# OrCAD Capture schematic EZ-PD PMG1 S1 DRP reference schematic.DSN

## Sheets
1 03. Step Down Regulators: size A3; title: PMG1-S1 DRP REFERENCE DESIGN; rev: 01; note: 630-XXXXX-XX
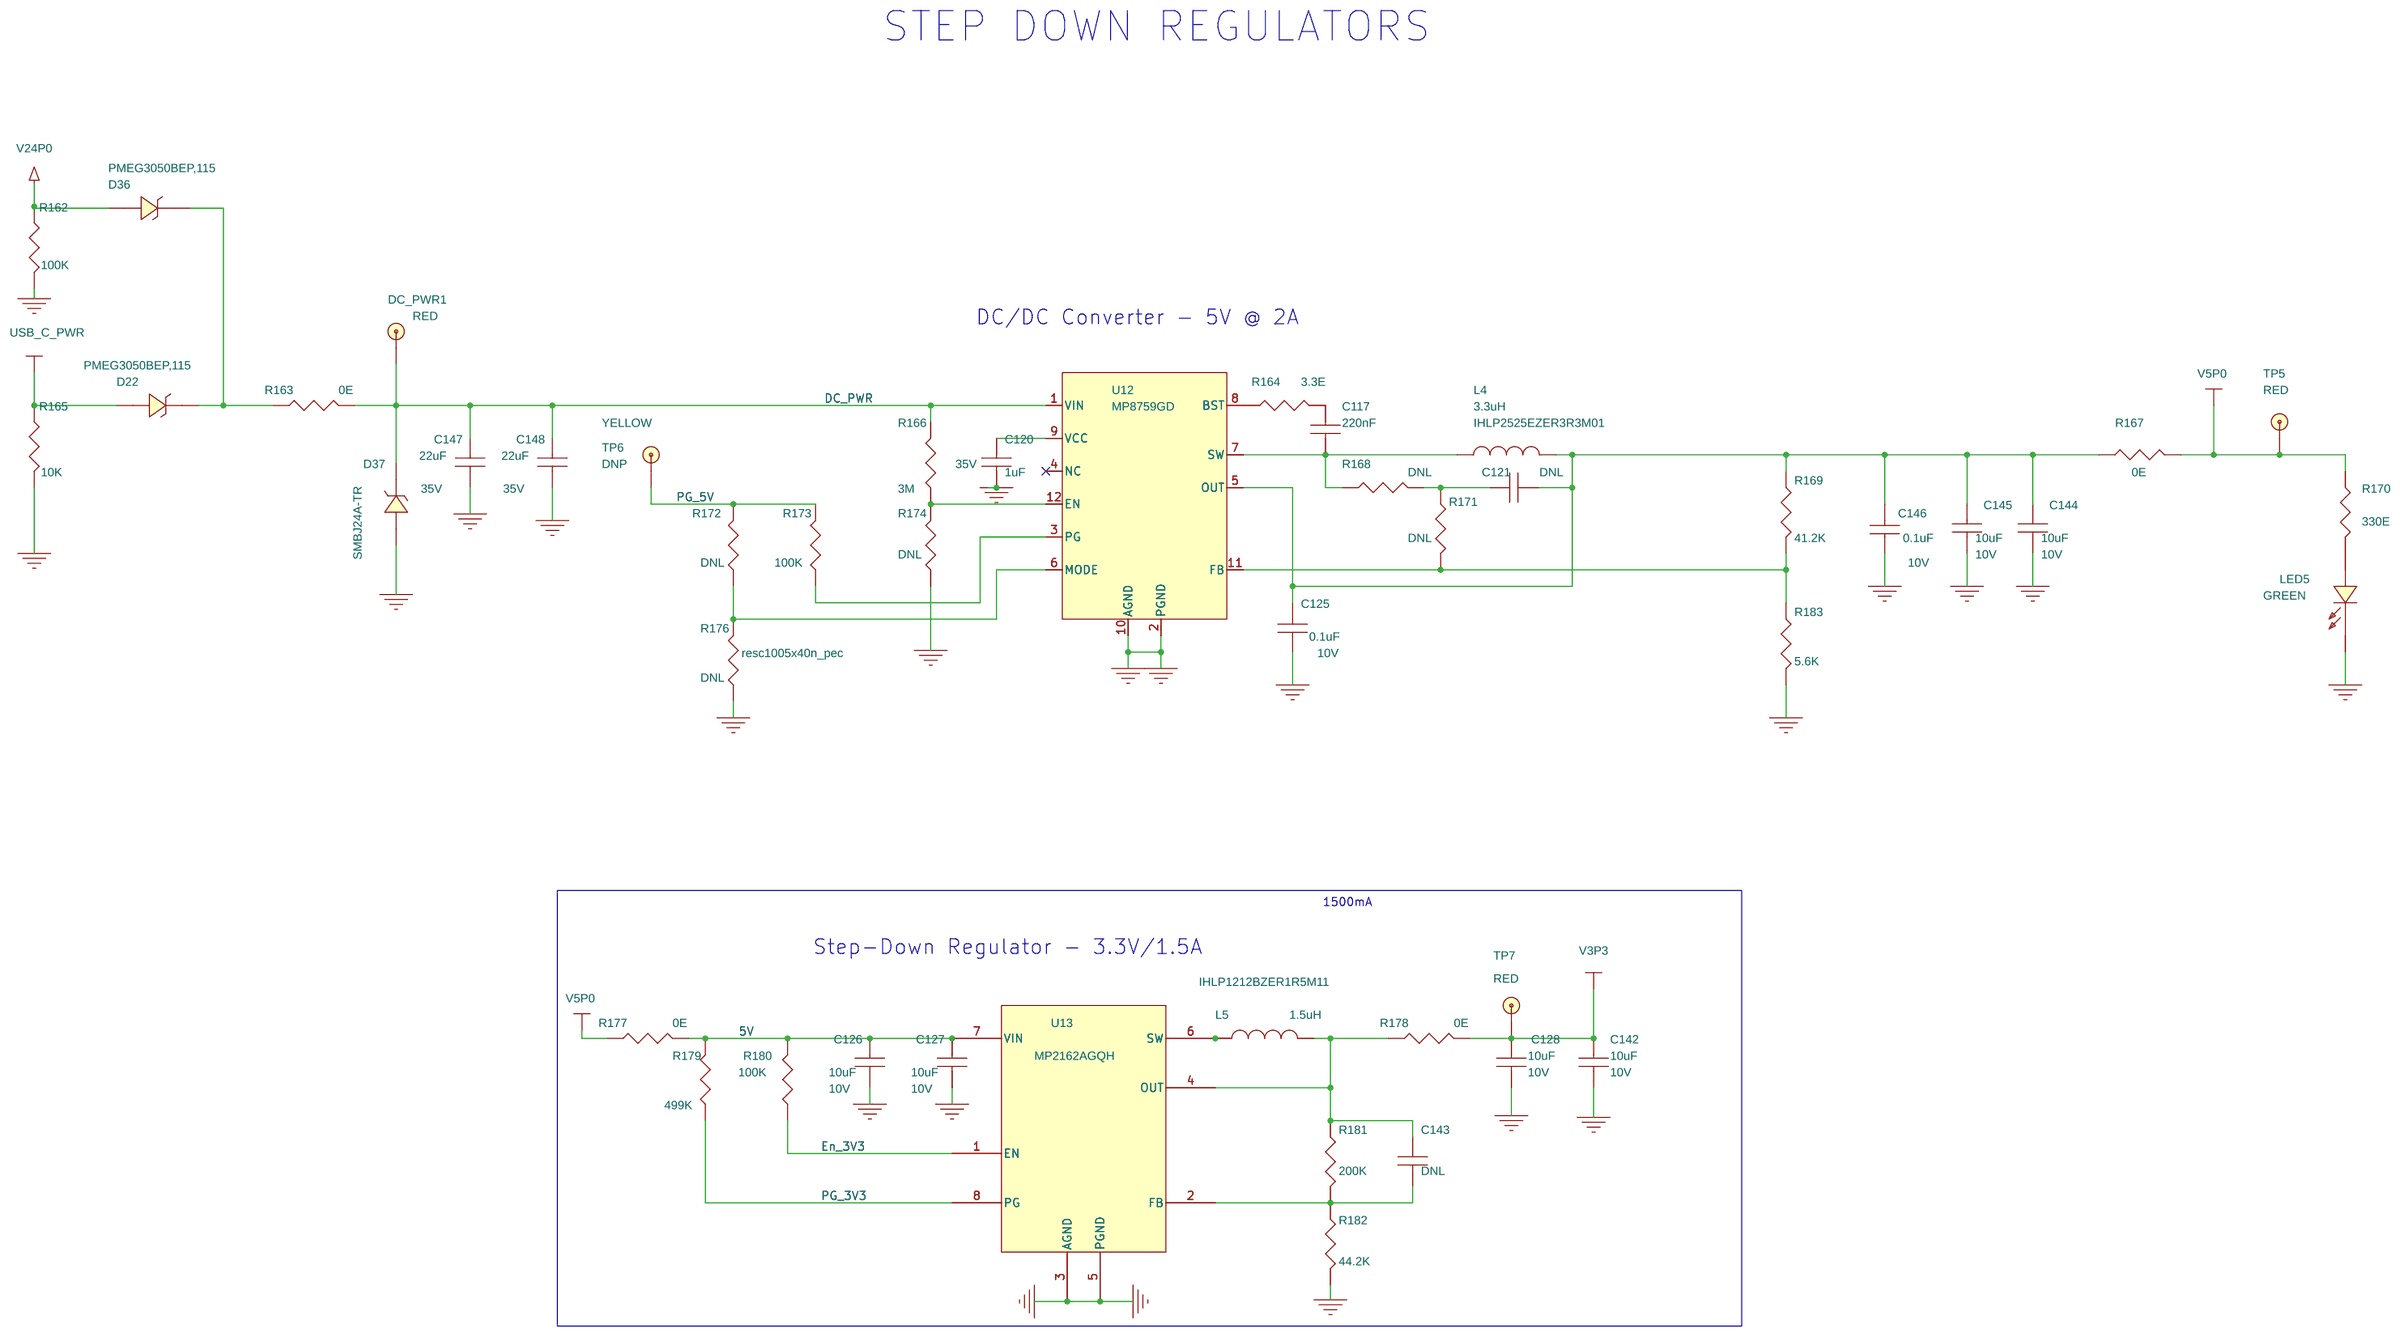
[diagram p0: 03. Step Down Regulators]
2 01. Title Page
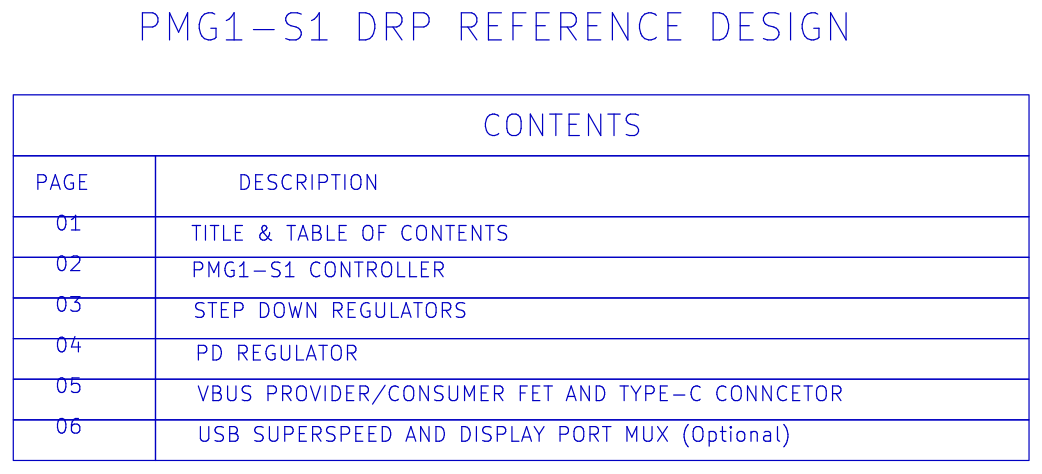
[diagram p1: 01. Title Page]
3 02. PMG1-S1 Controller: size A3
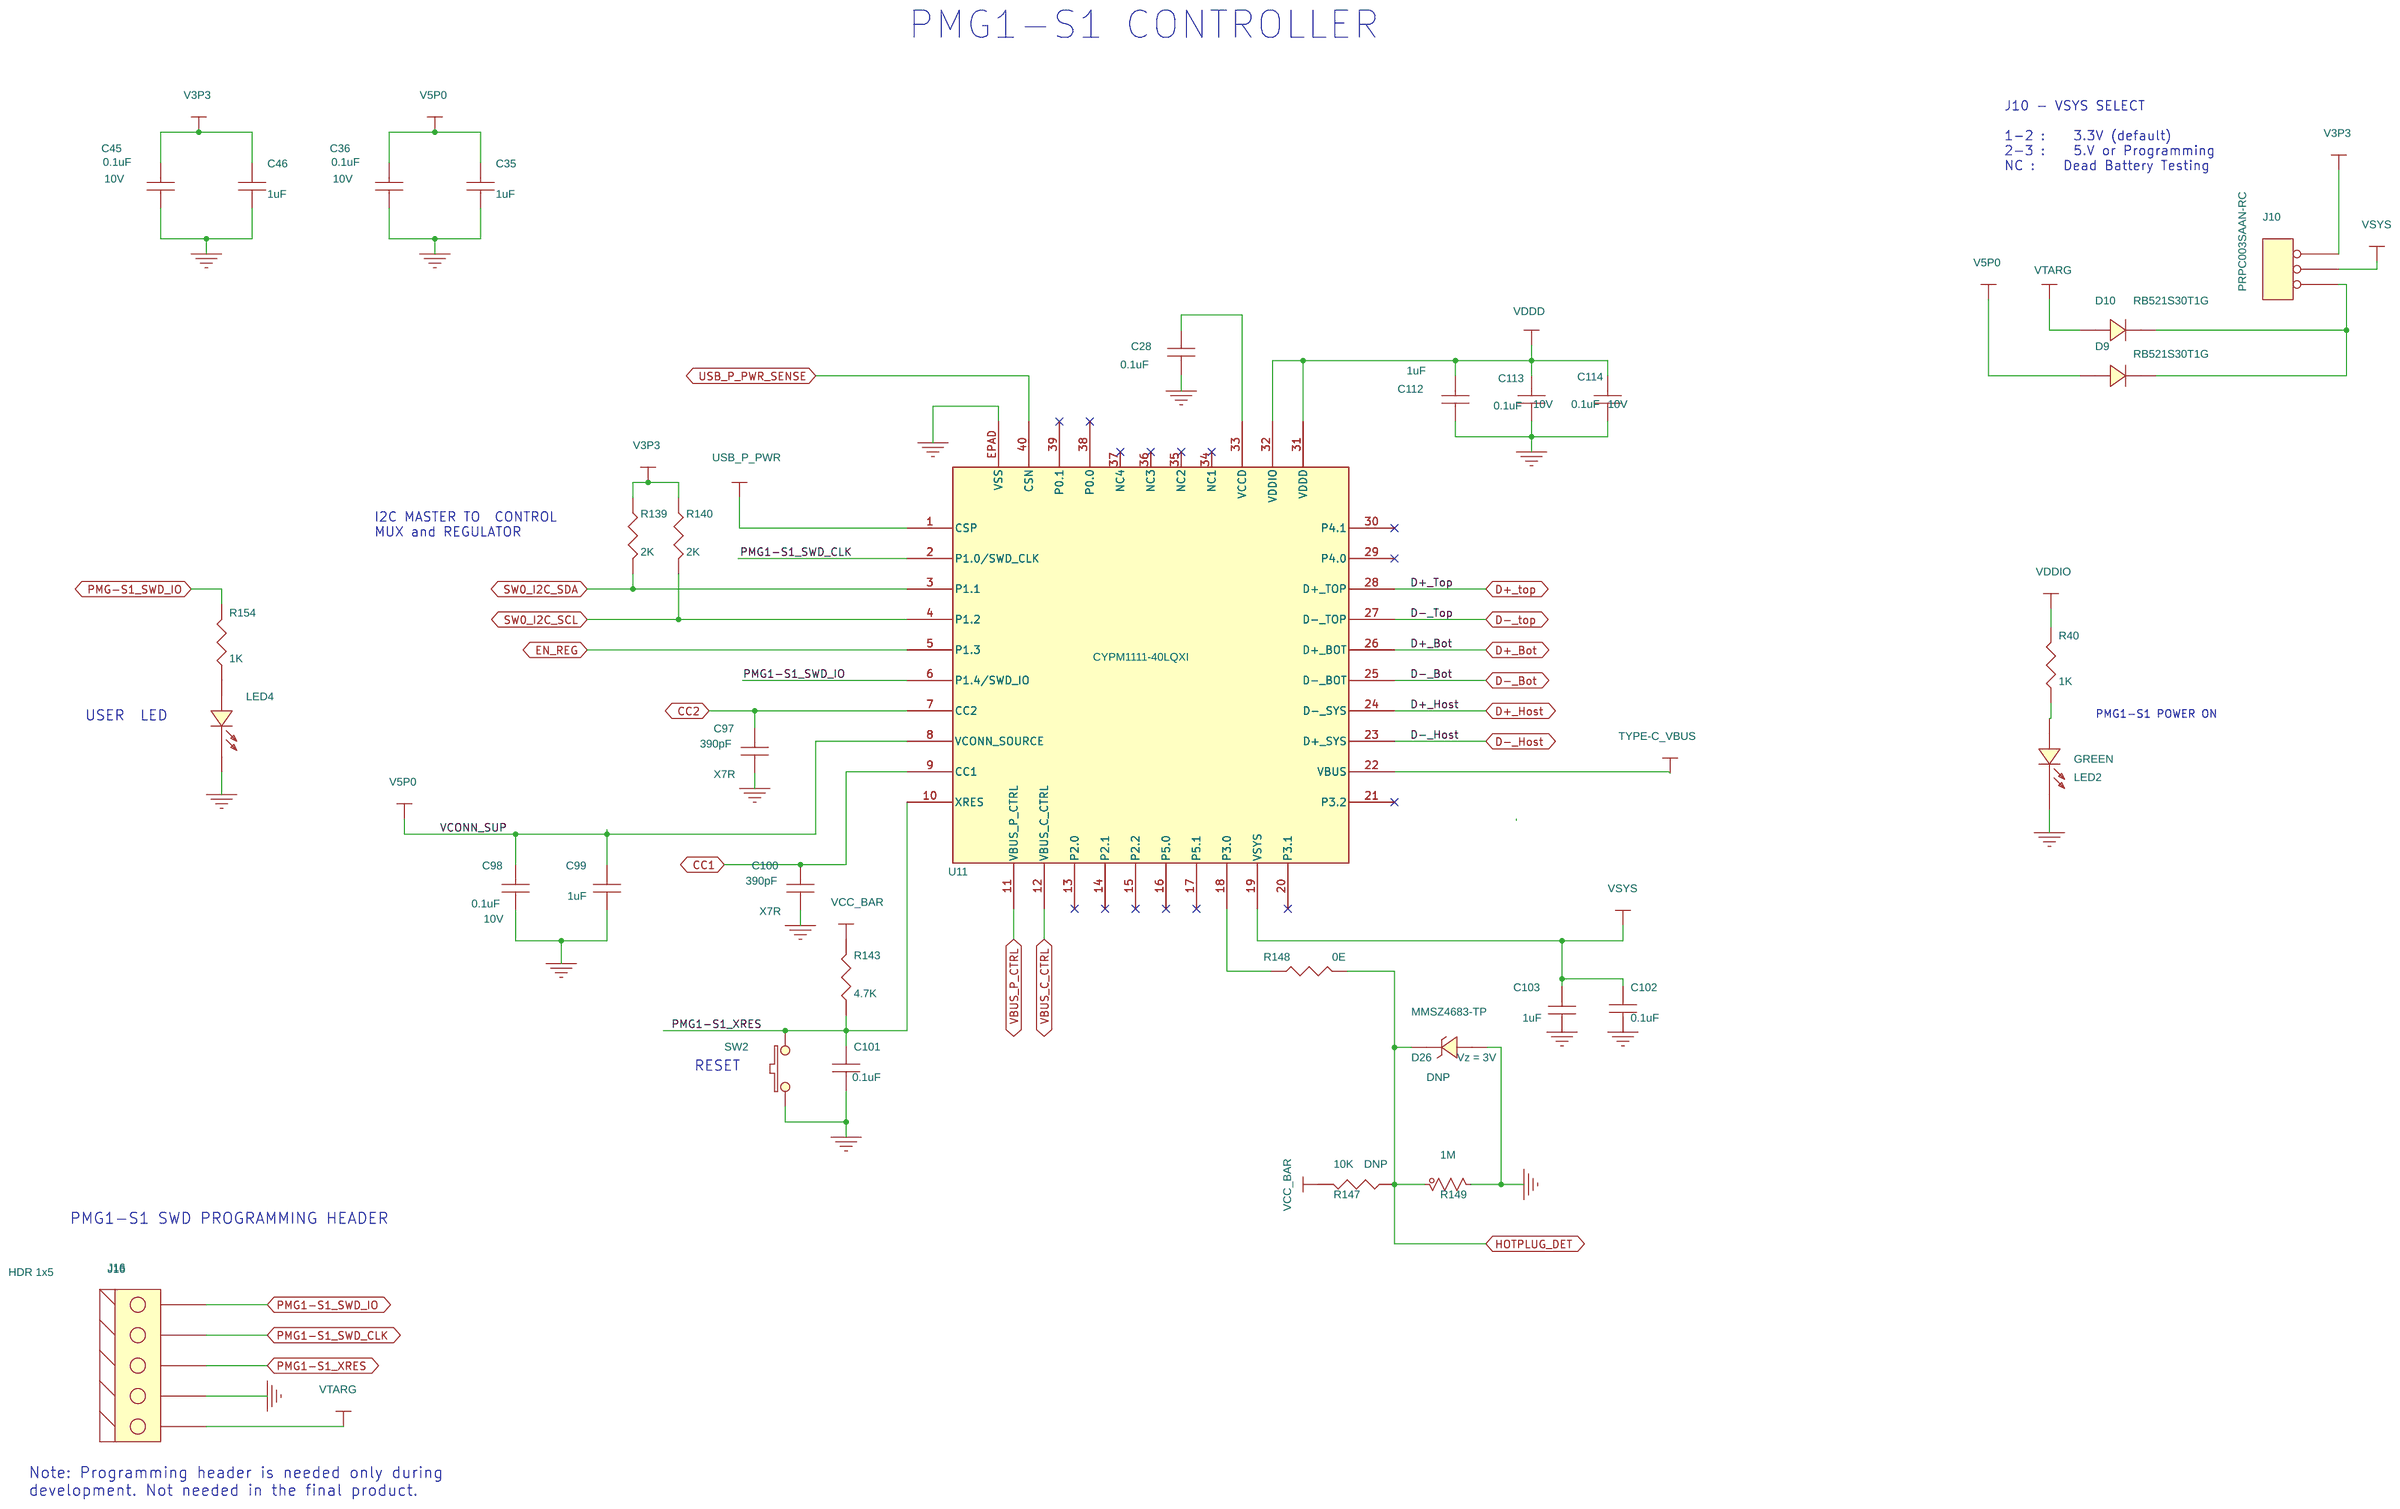
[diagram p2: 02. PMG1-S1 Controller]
4 06. PERICOM_MUX (OPTIONAL): size A3
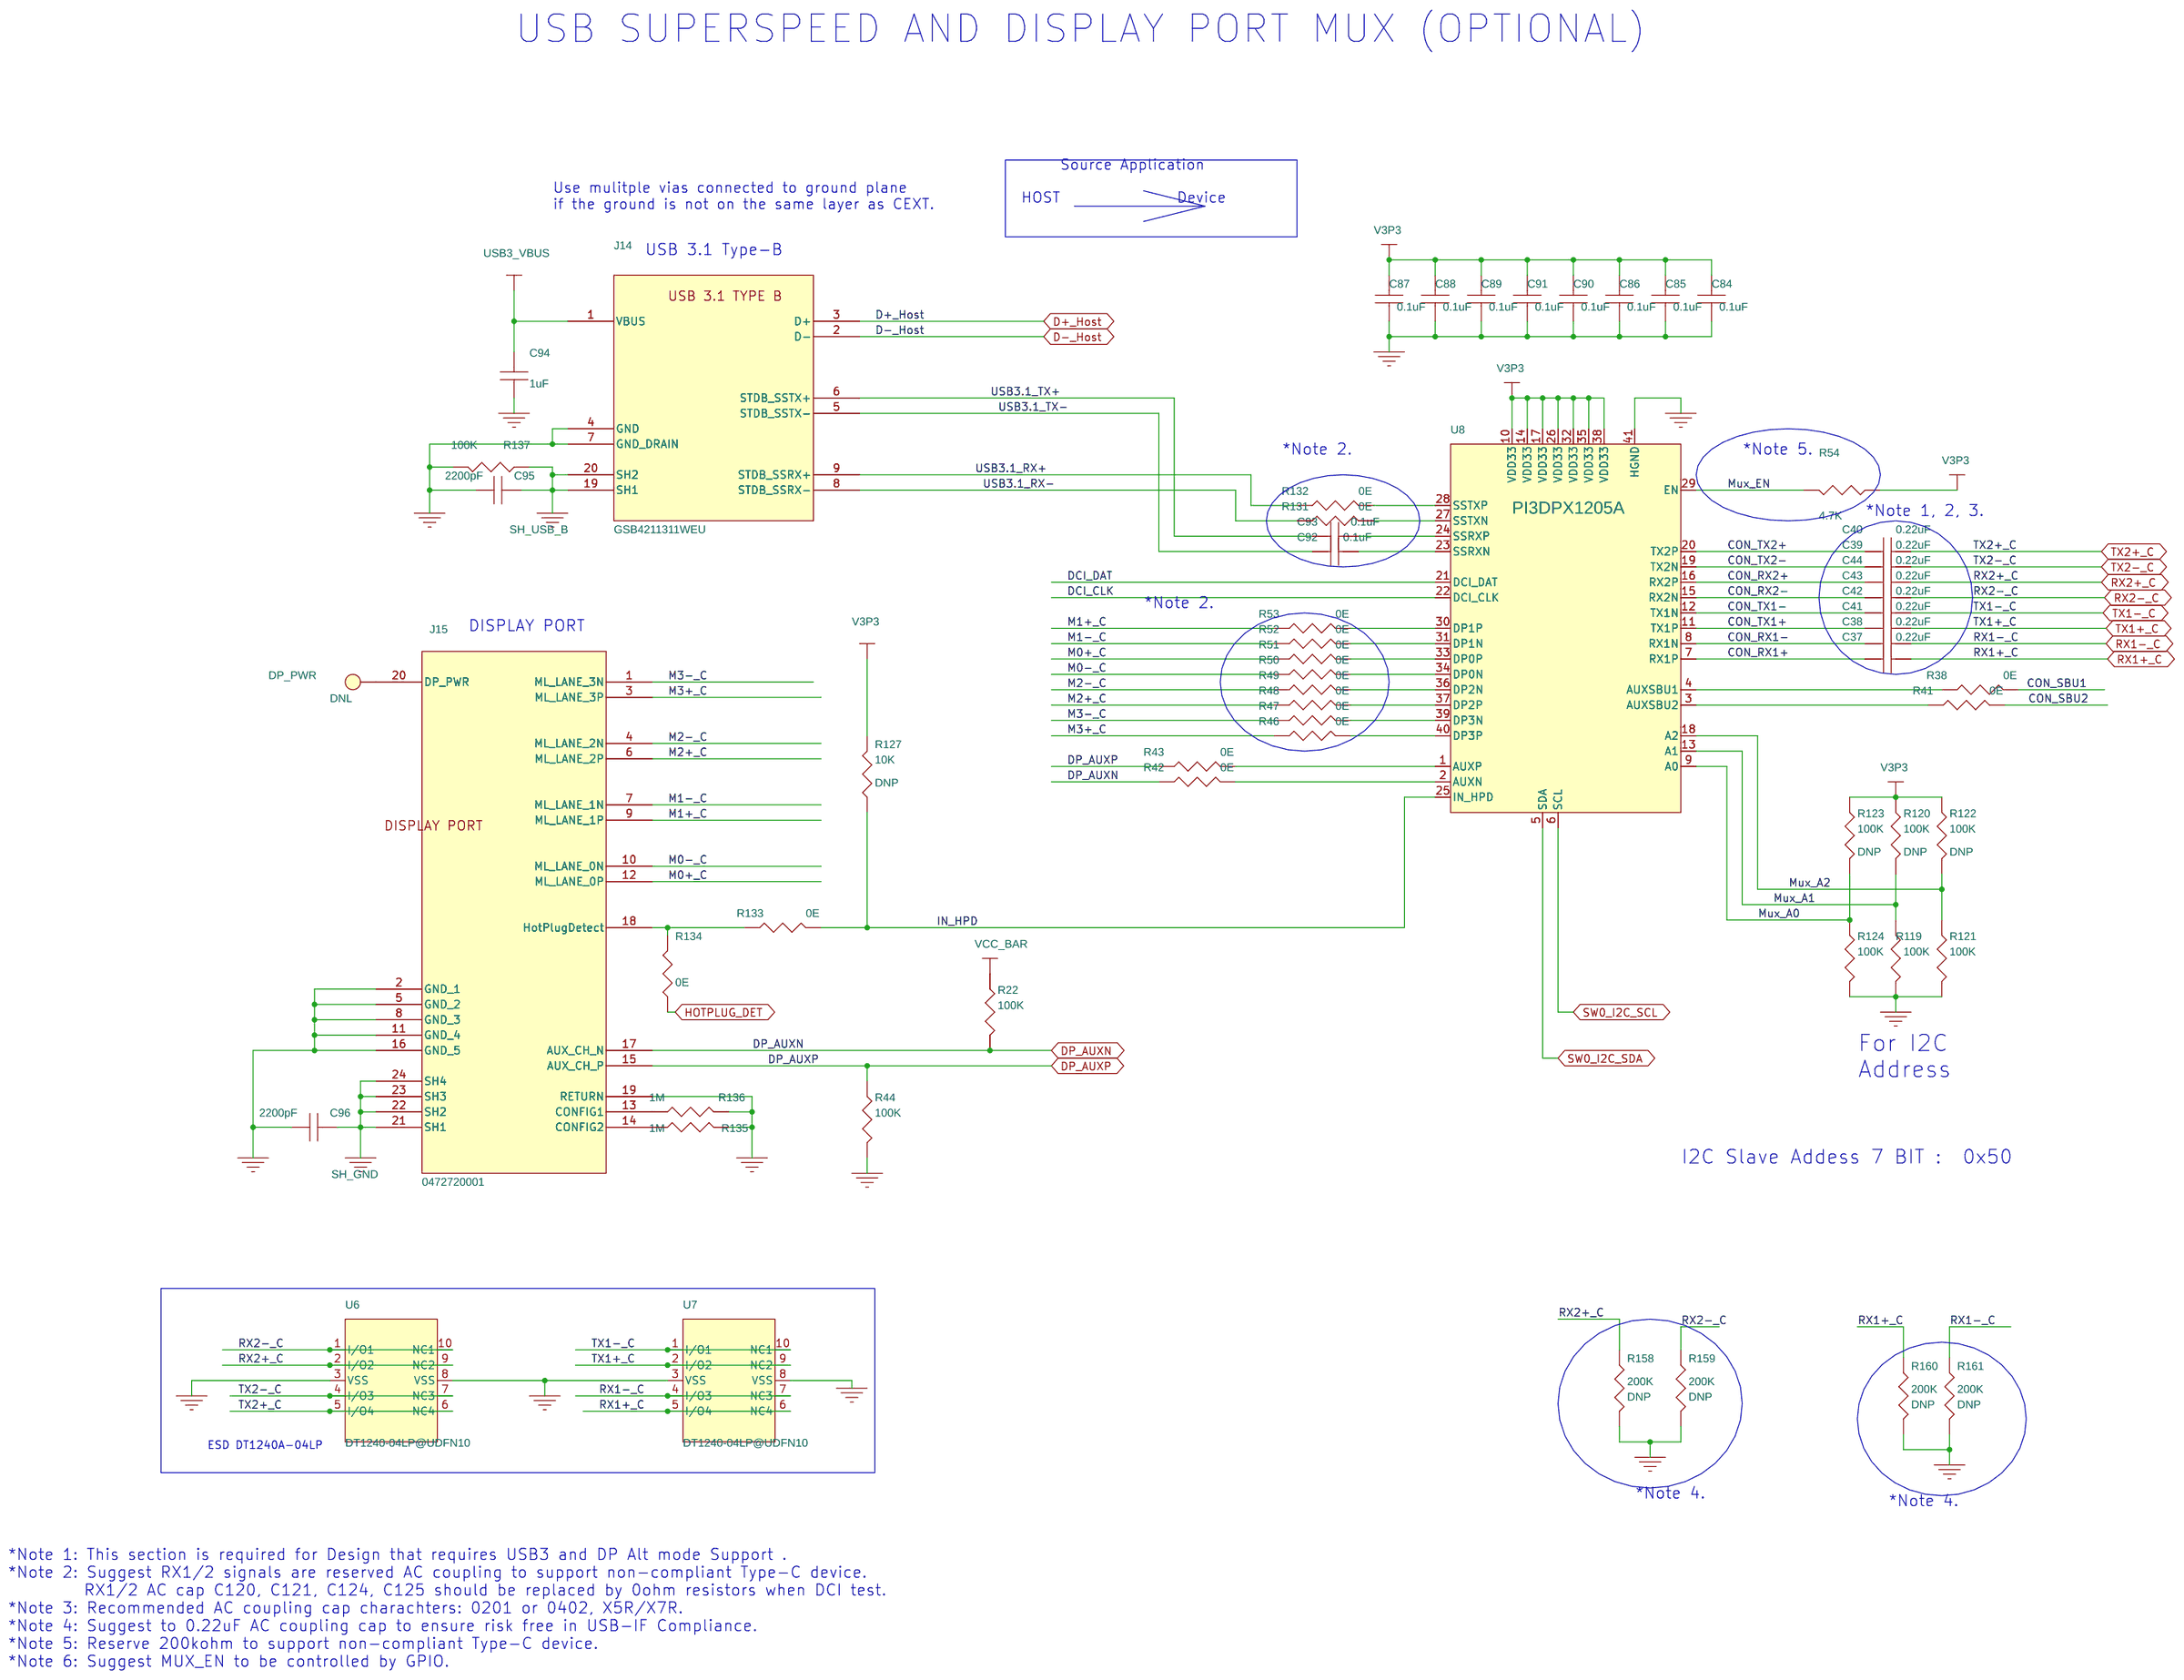
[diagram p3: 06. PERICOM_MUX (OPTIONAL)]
5 04 : PD Regulator: size A3
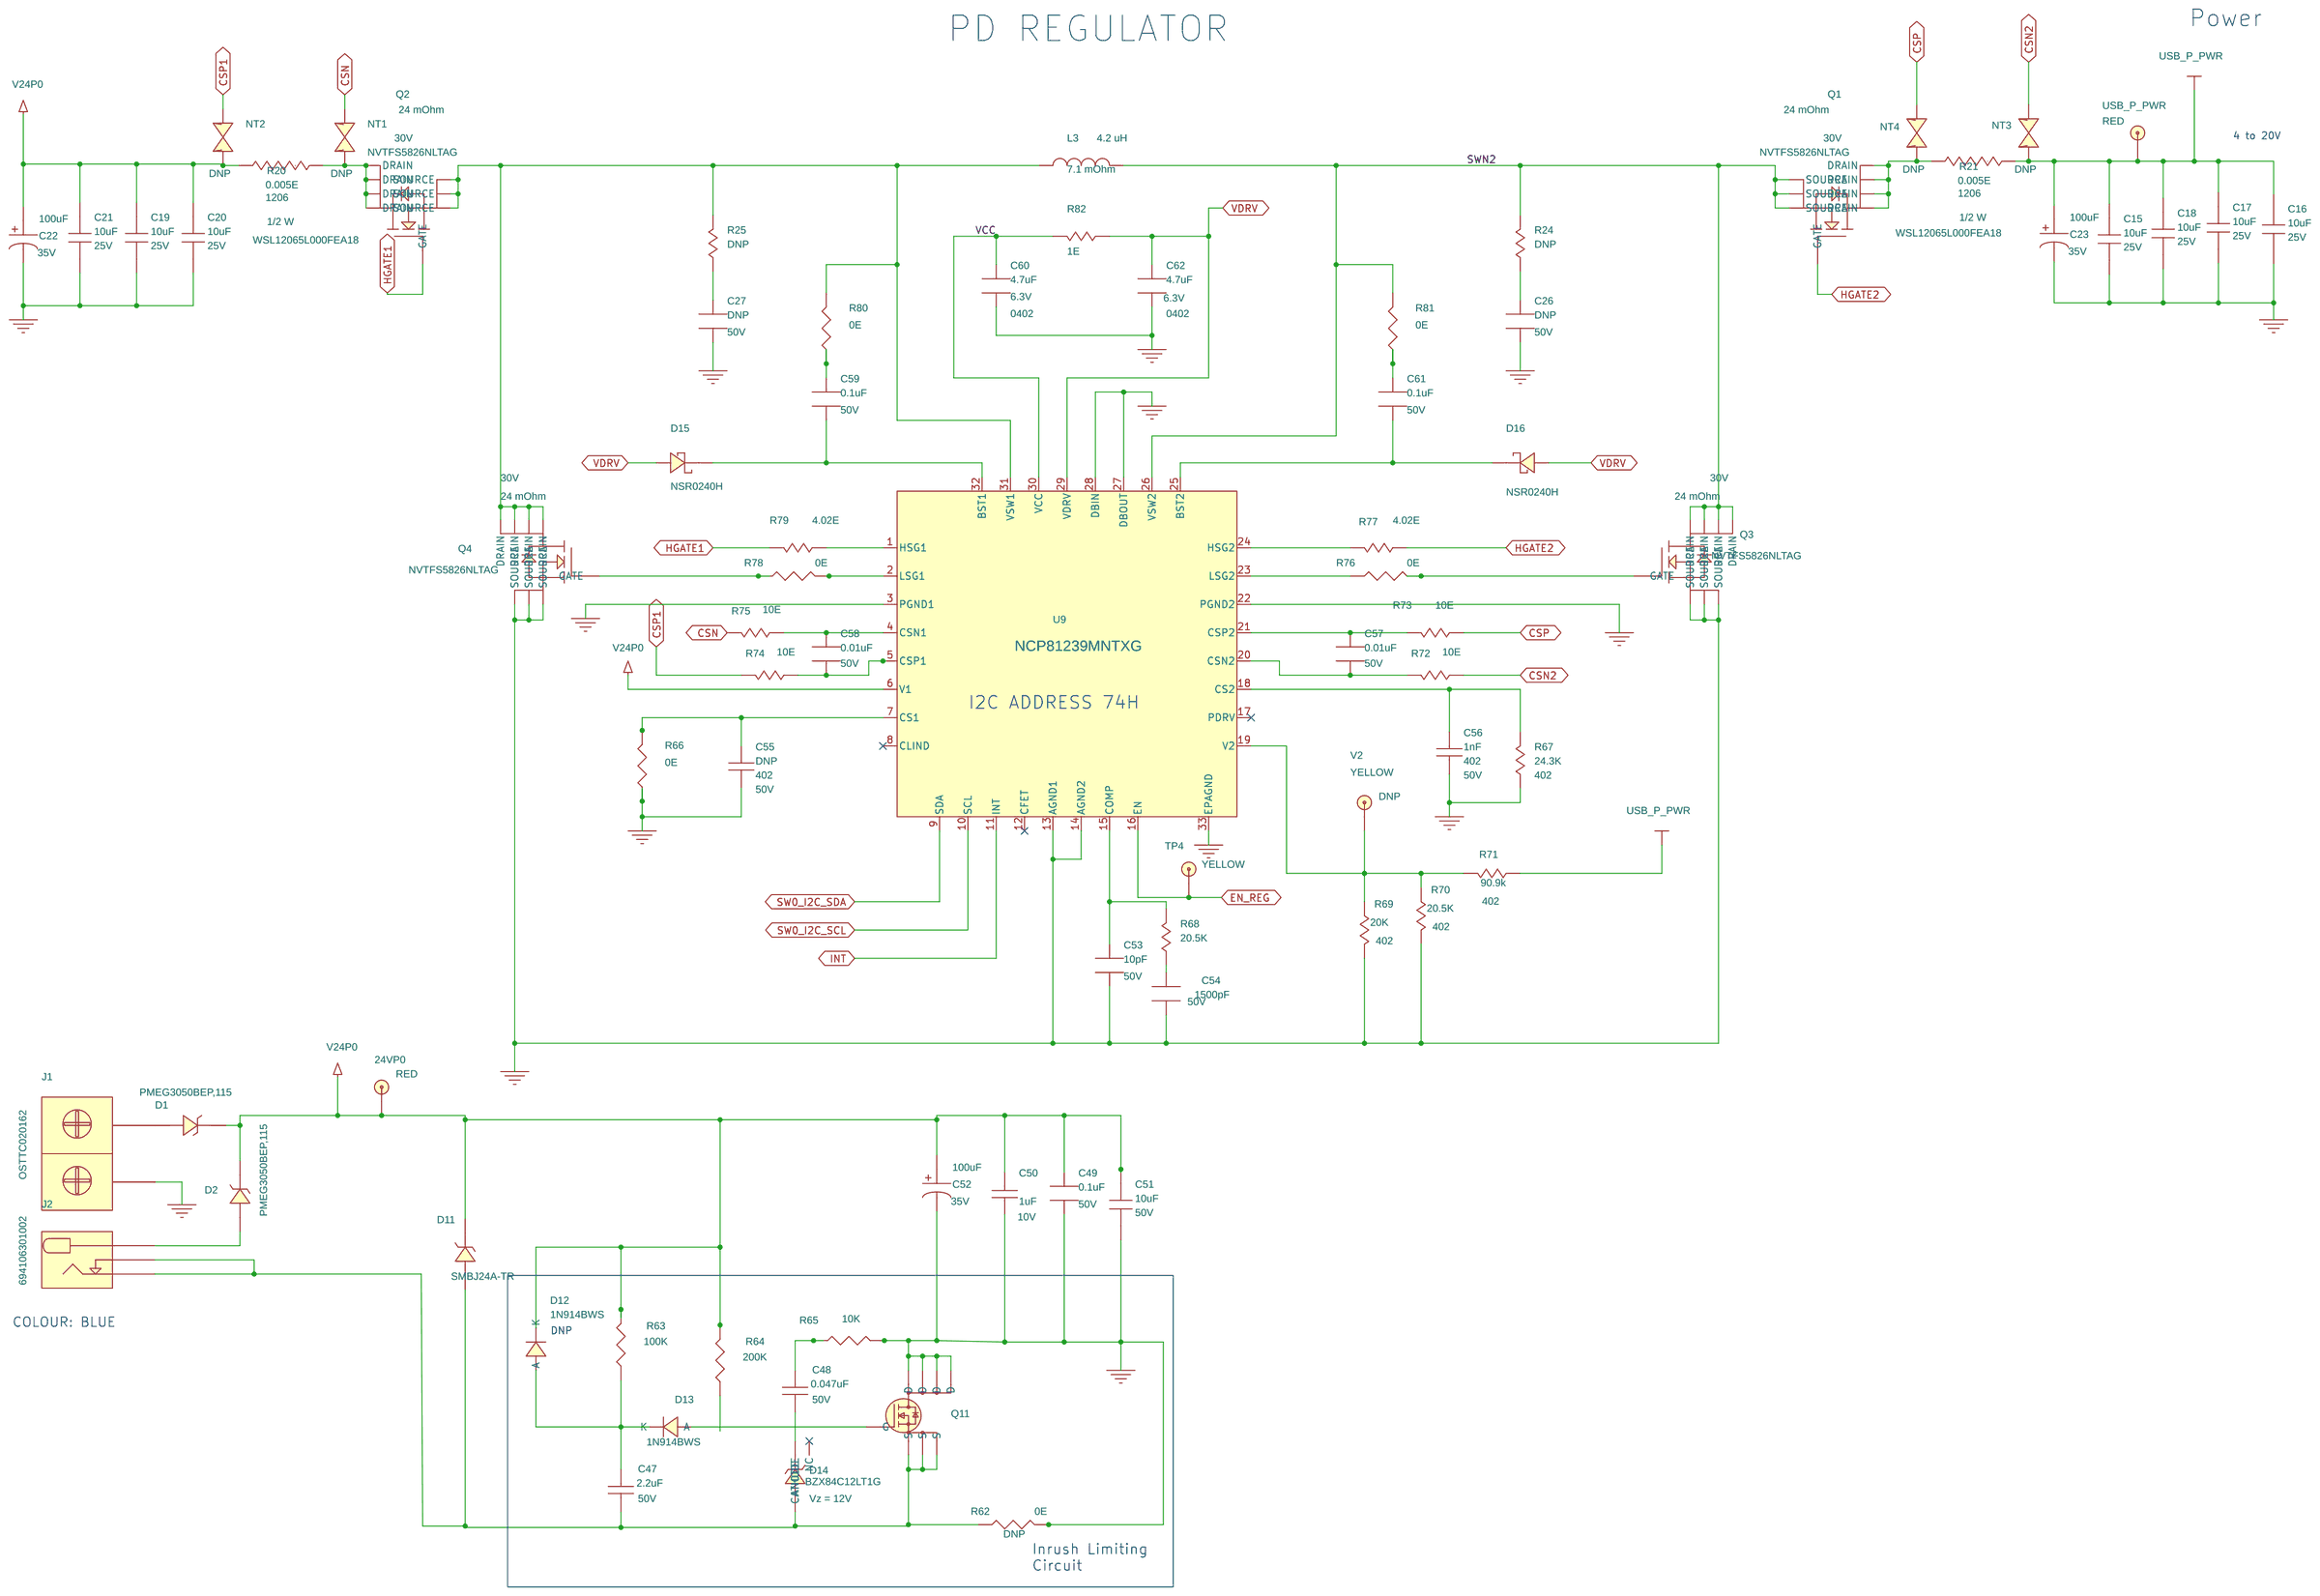
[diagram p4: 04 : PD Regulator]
6 05. VBUS Provider/Consumer: size A3
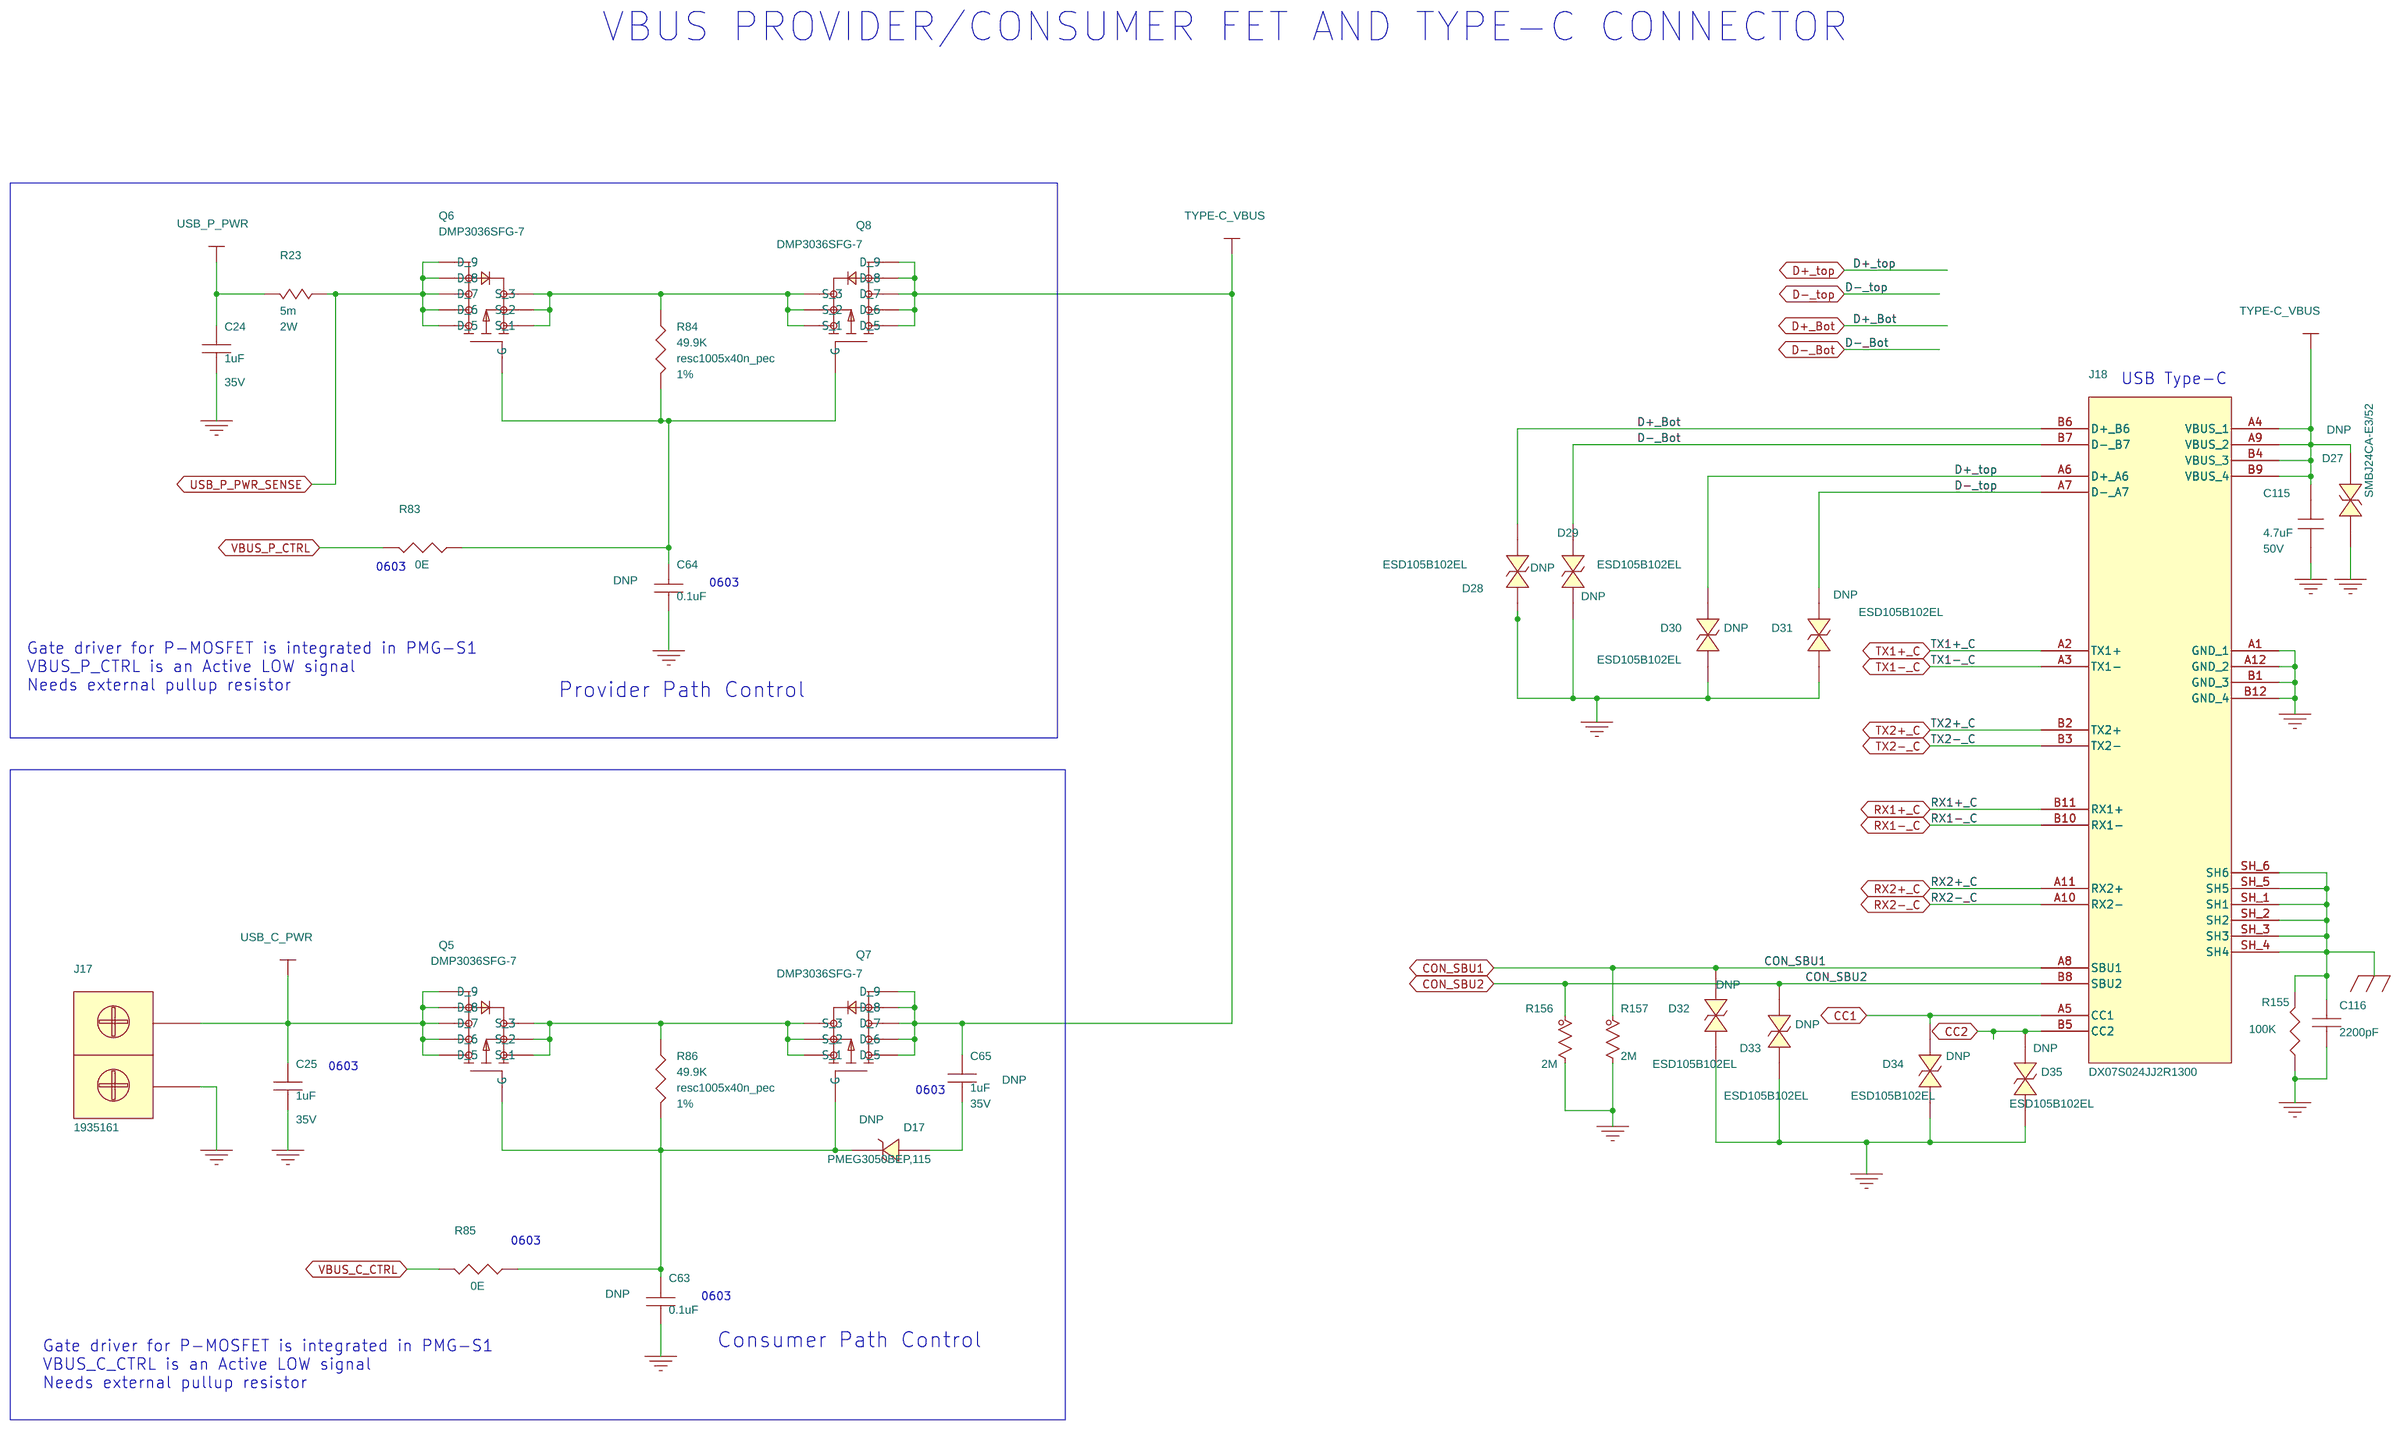
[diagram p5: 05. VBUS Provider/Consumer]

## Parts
sheet 02. PMG1-S1 Controller
C28  0.1uF  [capc1005x56n_cyps]
C35  1uF  [capc1005x56n_cyps]
C36  0.1uF  [capc1005x56n_cyps]
C45  0.1uF  [capc1005x56n_cyps]
C46  1uF  [capc1005x56n_cyps]
C97  390pF  [capc1608x90n_ty]
C98  0.1uF  [capc1005x56n_cyps]
C99  1uF  [capc1005x56n_cyps]
C100  390pF  [capc1608x90n_ty]
C101  0.1uF  [capc1005x56n_cyps]
C102  0.1uF  [capc1005x56n_cyps]
C103  1uF  [capc1005x56n_cyps]
C112  1uF  [capc1005x56n_cyps]
C113  0.1uF  [capc1005x56n_cyps]
C114  0.1uF  [capc1005x56n_cyps]
D9  RB521S30T1G  [RB521S30T1G-SOD523]
D10  RB521S30T1G  [RB521S30T1G-SOD523]
D26  MMSZ4683-TP  [SOD123_MMSZ4702T1G]
J10  PRPC003SAAN-RC  [hdr3x1]
J16  HDR 1x5  [HDR5_KEYED_M]
LED2  GREEN  [ledc1608x80n]
LED4  ORANGE  [ledc1608x80n]
R40  1K  [resc2012x70n_pec]
R139  2K  [resc1005x40n_pec]
R140  2K  [resc1005x40n_pec]
R143  4.7K  [resc1005x40n_pec]
R147  10K  [resc1005x40n_pec]
R148  0E  [RESC2012X70N_PEC]
R149  1M  [resc1005x40n_pec]
R154  1K  [resc2012x70n_pec]
SW2  EVQ-PE105K  [switch-evq-pe105k_5mm]
U11  CYPM1111-40LQXI  [qfn50p600x600x60-41m]
sheet 03. Step Down Regulators
C117  220nF  [capc1005x56n_cyps]
C120  1uF  [capc1608x90n_ty]
C121  DNP  [capc1005x56n_cyps]
C125  0.1uF  [capc1005x56n_cyps]
C126  10uF  [CAPC1608X90N_TY]
C127  10uF  [CAPC1608X90N_TY]
C128  10uF  [CAPC1608X90N_TY]
C142  10uF  [CAPC1608X90N_TY]
C143  DNL  [capc1005x56n_cyps]
C144  10uF  [CAPC1608X90N_TY]
C145  10uF  [CAPC1608X90N_TY]
C146  0.1uF  [capc1005x56n_cyps]
C147  22uF  [WSL1206]
C148  22uF  [WSL1206]
D22  PMEG3050BEP,115  [SOD128]
D36  PMEG3050BEP,115  [SOD128]
D37  SMBJ24A-TR  [SMBJ24A-TR]
DC_PWR1  RED  [TP-43R_S]
L4  3.3uH  [IHLP2525EZER3R3M01]
L5  1.5uH  [IHLP1212AEER1R5M11]
LED5  GREEN  [ledc1608x80n]
R162  100K  [resc1005x40n_pec]
R163  0E  [RESC2012X70N_PEC]
R164  3.3E  [RESC1005X40N_PEC]
R165  10K  [resc1005x40n_pec]
R166  3M  [resc1005x40n_pec]
R167  0E  [RESC2012X70N_PEC]
R168  DNP  [RESC1005X40N_PEC]
R169  41.2K  [RESC1005X40N_PEC]
R170  330E  [resc1608x55n_pec]
R171  DNP  [RESC1005X40N_PEC]
R172  DNL  [resc1005x40n_pec]
R173  100K  [resc1005x40n_pec]
R174  R  [RESC1005X40N_PEC]
R176  DNL  [resc1005x40n_pec]
R177  0E  [RESC2012X70N_PEC]
R178  0E  [RESC2012X70N_PEC]
R179  499K  [RESC1005X40N_PEC]
R180  100K  [resc1005x40n_pec]
R181  200K  [RESC1005X40N_PEC]
R182  44.2K  [RESC1005X40N_PEC]
R183  5.6K  [RESC1005X40N_PEC]
TP5  RED  [TP-43R_S]
TP6  YELLOW  [TP-43R_S]
TP7  RED  [TP-43R_S]
U12  MP8759GD  [QFN12_2X3mm]
U13  MP2162AGQH  [QFN8_2P0X1P5]
sheet 04 : PD Regulator
24VP0  RED  [TP-43R_S]
C15  10uF  [capc2012x70n_murata]
C16  10uF  [capc2012x70n_murata]
C17  10uF  [capc2012x70n_murata]
C18  10uF  [capc2012x70n_murata]
C19  10uF  [capc2012x70n_murata]
C20  10uF  [capc2012x70n_murata]
C21  10uF  [capc2012x70n_murata]
C22  100uF  [CAP_RADIAL_8MM-3_5MM]
C23  100uF  [CAP_RADIAL_8MM-3_5MM]
C26  DNP  [capc1005x56n_cyps]
C27  DNP  [capc1005x56n_cyps]
C47  2.2uF  [capc2012X70N_MURATA]
C48  0.047uF  [CAPC1608X90N_TY]
C49  0.1uF  [capc1005x56n_cyps]
C50  1uF  [capc1005x56n_cyps]
C51  10uF  [WSL1206]
C52  100uF  [CAP_RADIAL_8MM-3_5MM]
C53  10pF  [capc1005x56n_cyps]
C54  1500pF  [capc1005x56n_cyps]
C55  DNP  [capc1005x56n_cyps]
C56  1nF  [capc1005x56n_cyps]
C57  0.01uF  [capc1005x56n_cyps]
C58  0.01uF  [capc1005x56n_cyps]
C59  0.1uF  [capc1005x56n_cyps]
C60  4.7uF  [capc1005x56n_cyps]
C61  0.1uF  [capc1005x56n_cyps]
C62  4.7uF  [capc1005x56n_cyps]
D1  PMEG3050BEP,115  [SOD128]
D2  PMEG3050BEP,115  [SOD128]
D11  SMBJ24A-TR  [DIOM5336X262N]
D12  1N914BWS  [SOD323F]
D13  1N914BWS  [SOD323F]
D14  BZX84C12LT1G  [SOT95P240X111-3N]
D15  NSR0240H  [CRSMI_SOD323]
D16  NSR0240H  [CRSMI_SOD323]
J1  OSTTC020162  [TERMINAL_BLOCK_2PIN]
J2  694106301002  [RAPC712]
L3  4.2 uH  [XENTRIS_IND_WURTH_10MMX10MM]
NT1  Net tie  [net_tie]
NT2  Net tie  [net_tie]
NT3  Net tie  [net_tie]
NT4  Net tie  [net_tie]
Q1  NVTFS5826NLTAG  [USMM_WDFN08_3P3X3P3X0P65P]
Q2  NVTFS5826NLTAG  [USMM_WDFN08_3P3X3P3X0P65P]
Q3  NVTFS5826NLTAG  [USMM_WDFN08_3P3X3P3X0P65P]
Q4  NVTFS5826NLTAG  [USMM_WDFN08_3P3X3P3X0P65P]
Q11  BSZ110N06NS3 G  [TSDSON65P330X330X100-8N]
R20  0.005E  [WSL1206]
R21  0.005E  [WSL1206]
R24  DNP  [RESC1005X40N_PEC]
R25  DNP  [RESC1005X40N_PEC]
R62  0E  [RESC2012X70N_PEC]
R63  100K  [resc1608x55n_pec]
R64  200K  [resc1608x55n_pec]
R65  10K  [resc1005x40n_pec]
R66  0E  [resc1005x40n_pec]
R67  24.3K  [resc1005x40n_pec]
R68  20.5K  [resc1005x40n_pec]
R69  20K  [resc1005x40n_pec]
R70  20.5K  [resc1005x40n_pec]
R71  90.9k  [resc1005x40n_pec]
R72  10E  [resc1005x40n_pec]
R73  10E  [resc1005x40n_pec]
R74  10E  [resc1005x40n_pec]
R75  10E  [resc1005x40n_pec]
R76  0E  [resc1005x40n_pec]
R77  4.02E  [resc1005x40n_pec]
R78  0E  [resc1005x40n_pec]
R79  4.02E  [resc1005x40n_pec]
R80  0E  [resc1005x40n_pec]
R81  0E  [resc1005x40n_pec]
R82  1E  [resc1005x40n_pec]
TP4  YELLOW  [TP-43R_S]
U9  NCP81239MNTXG  [USMM_QFN32R5X5]
USB_P_PWR  RED  [TP-43R_S]
V2  YELLOW  [TP-43R_S]
sheet 05. VBUS Provider/Consumer
C24  1uF  [capc1608x90n_ty]
C25  1uF  [capc1608x90n_ty]
C63  0.1uF  [capc1005x56n_cyps]
C64  0.1uF  [capc1005x56n_cyps]
C65  1uF  [capc1608x90n_ty]
C115  4.7uF  [capc3225x280n_tdk]
C116  2200pF  [C1808]
D17  PMEG3050BEP,115  [PMEG3050EP-115]
D27  SMBJ24CA-E3/52  [SMBJ24CA_3P679_2H44]
D28  ESD105B102EL  [ESD_TSLP2_0P65_0H4]
D29  ESD105B102EL  [ESD_TSLP2_0P65_0H4]
D30  ESD105B102EL  [ESD_TSLP2_0P65_0H4]
D31  ESD105B102EL  [ESD_TSLP2_0P65_0H4]
D32  ESD105B102EL  [ESD_TSLP2_0P65_0H4]
D33  ESD105B102EL  [ESD_TSLP2_0P65_0H4]
D34  ESD105B102EL  [ESD_TSLP2_0P65_0H4]
D35  ESD105B102EL  [ESD_TSLP2_0P65_0H4]
J17  1935161  [1935161]
J18  DX07S024JJ2R1300  [USB-PD_TYPE-C]
Q5  DMP3036SFG-7  [MOSFET_DMP3036SFG-7]
Q6  DMP3036SFG-7  [MOSFET_DMP3036SFG-7]
Q7  DMP3036SFG-7  [MOSFET_DMP3036SFG-7]
Q8  DMP3036SFG-7  [MOSFET_DMP3036SFG-7]
R23  5m  [RESC6432X65N_SPE]
R83  0E  [resc1005x40n_pec]
R84  49.9K  [resc1005x40n_pec]
R85  0E  [resc1005x40n_pec]
R86  49.9K  [resc1005x40n_pec]
R155  100K  [resc1005x40n_pec]
R156  2M  [resc1005x40n_pec]
R157  2M  [resc1005x40n_pec]
sheet 06. PERICOM_MUX (OPTIONAL)
C37  0.22uF  [capc1005x56n_cyps]
C38  0.22uF  [capc1005x56n_cyps]
C39  0.22uF  [capc1005x56n_cyps]
C40  0.22uF  [capc1005x56n_cyps]
C41  0.22uF  [capc1005x56n_cyps]
C42  0.22uF  [capc1005x56n_cyps]
C43  0.22uF  [capc1005x56n_cyps]
C44  0.22uF  [capc1005x56n_cyps]
C84  0.1uF  [capc1005x56n_cyps]
C85  0.1uF  [capc1005x56n_cyps]
C86  0.1uF  [capc1005x56n_cyps]
C87  0.1uF  [capc1005x56n_cyps]
C88  0.1uF  [capc1005x56n_cyps]
C89  0.1uF  [capc1005x56n_cyps]
C90  0.1uF  [capc1005x56n_cyps]
C91  0.1uF  [capc1005x56n_cyps]
C92  0.1uF  [capc1005x56n_cyps]
C93  0.1uF  [capc1005x56n_cyps]
C94  1uF  [capc1005x56n_cyps]
C95  2200pF  [C1808]
C96  2200pF  [C1808]
DP_PWR  RED  [TP-43R_S]
J14  GSB4211311WEU  [USB_CONN_GSB3211311WEU]
J15  0472720001  [CONN20_0472720001]
R22  100K  [resc1005x40n_pec]
R38  0E  [resc1005x40n_pec]
R41  0E  [resc1005x40n_pec]
R42  0E  [resc1005x40n_pec]
R43  0E  [resc1005x40n_pec]
R44  100K  [resc1005x40n_pec]
R46  0E  [resc1005x40n_pec]
R47  0E  [resc1005x40n_pec]
R48  0E  [resc1005x40n_pec]
R49  0E  [resc1005x40n_pec]
R50  0E  [resc1005x40n_pec]
R51  0E  [resc1005x40n_pec]
R52  0E  [resc1005x40n_pec]
R53  0E  [resc1005x40n_pec]
R54  4.7K  [resc1005x40n_pec]
R119  100K  [resc1005x40n_pec]
R120  100K  [resc1005x40n_pec]
R121  100K  [resc1005x40n_pec]
R122  100K  [resc1005x40n_pec]
R123  100K  [resc1005x40n_pec]
R124  100K  [resc1005x40n_pec]
R127  10K  [resc1005x40n_pec]
R131  0E  [resc1005x40n_pec]
R132  0E  [resc1005x40n_pec]
R133  0E  [resc1005x40n_pec]
R134  0E  [resc1005x40n_pec]
R135  1M  [resc1608x55n_pec]
R136  1M  [resc1608x55n_pec]
R137  100K  [resc1005x40n_pec]
R158  200K  [RESC1005X40N_PEC]
R159  200K  [RESC1005X40N_PEC]
R160  200K  [RESC1005X40N_PEC]
R161  200K  [RESC1005X40N_PEC]
U6  DT1240-04LP@UDFN10  [DT1240-04LP-7_10DFN]
U7  DT1240-04LP@UDFN10  [DT1240-04LP-7_10DFN]
U8  PI3DPX1205A  [QFN40P400X600X80-41T475X275N]

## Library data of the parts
C28 = CAP_NP: CAP CER 0.1UF 10V 10% X7R 0402; Alternate Manufacturer: TDK Corporation; Alternate Mfr Part #: C1005X7R1C104K050BC; DIGI-KEY PART NO: 490-3890-1-ND; MFG Part number: C1005X7R1A104K050BB; Manufacturer: TDK Corporation; Price: 0.1; Voltage: 10V
C35 C46 C50 C94 C99 C103 C112 = CAP_NP: CAP CER 1UF 10V X5R 0402; Alternate Manufacturer: TDK Corporation; Alternate Mfr Part #: C1005X7S1A105K050BC; DIGI-KEY PART NO: 490-3890-1-ND; MFG Part number: GRM155R61A105KE15D; Manufacturer: Murata Electronics North America; Price: 0.1; Voltage: 10V
C36 C45 C98 C113 C114 = CAP_NP: CAP CER 0.1UF 10V 10% X7R 0402; Alternate Manufacturer: Samsung Electro-Mechanics; Alternate Mfr Part #: CL05B104KP5NNNC; MFG Part Number: C1005X7R1A104K050BB; Manufacturer: TDK Corporation; PART_NUMBER: C1005X7R1A104K050BB; RATED_VOLTAGE: 10V; Rating: 10V; Temp_Coefficient: X7R; Tolerance: 10%; VOLTAGE: 10V
C97 C100 = CAP-NP_0: CAP CER 390PF 50V 5% X7R 0603; MFG Part number: C0603C391J5RACTU; Manufacturer: Kemet; PART_NUMBER: C0603C391J5RACTU; RATED_VOLTAGE: 10V; Temp_Coefficient: X7R; Tolerance: 5%; VOLTAGE: 50V
C101 = CAP_NP: CAP CER 0.1UF 10V 10% X7R 0402; DIGI-KEY PART NO: 445-4958-1-ND; MFG Part number: C1005X7R1A104K050BB; Manufacturer: TDK Corporation; Price: 0.1; Voltage: 50V
C102 = CAP_NP: CAP CER 0.1UF 50V X7R 0402; DIGI-KEY PART NO: 445-5932-1-ND; MFG Part number: C1005X7R1H104K050BB; Manufacturer: TDK Corporation; Price: 0.15; Voltage: 50V
D9 D10 = DIODE_0: DIODE SCHOTTKY 30V 200MA SOD523; DIGI-KEY PART NO: RB521S30T1GOSCT-ND; Manufacturer: ON Semiconductor; Price: 0.2
D26 = DIO_ZENER_MMSZ4702T1G: DIODE ZENER 3V 500MW SOD123; DIGI-KEY PART NO: MMSZ4683-TPMSCT-ND; DNP: DNP; Manufacturer: Micro Commercial Co; Price: 0.21; Vz: 3V
J10 = CON3_0: CONN HEADER .100" SNGL STR 3POS; DIGI-KEY PART NO: S1011EC-03-ND; Manufacturer: Sullins Connector Solutions; Price: 0.18
J16 = 1X5_100MIL_HDR_4: CONN HEADER 5POS 0.1 VERT KEYED; BOM_IGNORE: REGULAR 100MIL HEADER; MFG PART NUMBER: 22-23-2051; Manufacturer: Molex; Mfr_Name: Molex; Mfr_Part_Number: 22-23-2051; PART_NUMBER: 22-23-2051
LED2 LED5 = LED_GREEN2_0: LED GREEN CLEAR 0603 SMD; DIGI-KEY PART NO: 160-1183-1-ND; MFG Part number: LTST-C190GKT; Manufacturer: Lite-On Inc.; Price: 0.28
LED4 = LED_GREEN2_0: LED ORANGE CLEAR 0603 SMD; DIGI-KEY PART NO: 160-1434-1-ND; MFG Part number: LTST-C190KFKT; Manufacturer: Lite-On Inc.; Price: 0.26
R40 R154 = RESD,0402,5%,1_32W,10K: RES SMD 1K OHM 5% 1/2W 0805; DIGI-KEY PART NO: P1.0KADCT-ND; MFG Part number: ERJ-P06J102V; Manufacturer: Panasonic Electronic Components; Price: 0.12; Tolerance: 5%
R139 R140 = RESISTOR_v2: RES SMD 2K OHM 5% 1/16W 0402; DIGI-KEY PART NO: 311-2.0KJRCT-ND; MFG Part number: RC0402JR-072KL; Manufacturer: Yageo; Price: 0.1; TOLERANCE: 5%
R54 R143 = RESISTOR_v2: RES SMD 4.7K OHM 5% 1/16W 0402; Alternate Manufacturer: Vishay Dale; Alternate Mfr Part #: CRCW04024K70JNED; DIGI-KEY PART NO: 311-4.7KJRCT-ND; MFG Part number: RC0402JR-074K7L; Manufacturer: Yageo; Price: 0.1; TOLERANCE: 5%
R147 = RESISTOR_v2: RES SMD 10K OHM 5% 1/16W 0402; DIGI-KEY PART NO: 311-2.0KJRCT-ND; DNP: DNP; MFG Part number: RC0402JR-0710KL; Manufacturer: Yageo; Price: 0.1; TOLERANCE: 5%
R148 R163 R167 R177 R178 = R: RES SMD 0.0 OHM JUMPER 1/8W 0805; DIGI-KEY PART NO: 311-0.0ARCT-ND; MFG Part number: RC0805JR-070RL; Manufacturer: Yageo; Price: 0.1
R149 = Res_0R_1_16W_Jumper_0402: RES SMD 1M OHM 1% 1/16W 0402; MFG Part number: ERJ-2RKF1004X; Manufacturer: Panasonic Electronic Components; Manufacturer Part Number: ERJ-2RKF1004X
SW2 = SW_PB_SPST: SWITCH TACTILE SPST-NO 0.05A 12V; DIGI-KEY PART NO: P13594SCT-ND; Manufacturer: Panasonic Electronic Components; Price: 0.72
U11 = CYPM1111-40LQXI_2: Power Delivery Microcontroller; Manufacturer: Cypress Semiconductor; Mfr_Name: Cypress Semiconductor
C117 = C_np: CAP CER 0.22UF 25V X5R 0402; MFG Part number: C1005X5R1E224K050BC; Manufacturer: TDK CORPORATION; Part No.: C1005X5R1E224K050BC
C24 C25 C120 = CAP_NP: CAP CER 1UF 35V X7R 0603; DIGI-KEY PART NO: 445-7414-1-ND; MFG Part number: C1608X7R1V105K080AC; Manufacturer: TDK Corporation; Price: 0.24; VOLTAGE: 35V
C121 = C_np: BOM_IG: NO LOAD; DNL: DNL; Part No.: C1005X5R0J105M050BB
C125 C146 = CAP_NP: CAP CER 0.1UF 10V 10% X7R 0402; Alternate Mfr #: CL05B104KP5NNNC; Alternate Mfr Part #: CL05B104KP5NNNC; Alternate manufacturer: Samsung Electro-Mechanics; MFG Part Number: C1005X7R1A104K050BB; Manufacturer: TDK Corporation; PART_NUMBER: C1005X7R1A104K050BB; RATED_VOLTAGE: 10V; Rating: 10V; Temp_Coefficient: X7R; Tolerance: 10%; VOLTAGE: 10V
C126-C128 C142 = C_np: CAP CER 10UF 10V 10% X5R 0603; MFG Part number: C1608X5R1A106K080AC; Manufacturer: TDK CORPORATION; Part No.: C1608X5R0J226M080AC; Voltage: 10V
C143 = C_np: BOM_IG: NO LOAD; Part No.: C1608X5R0J226M080AC; Voltage: 10V
C144 C145 = C_np: CAP CER 10UF 10V 10% X5R 0603; Descriptions: CAP CER 22UF 35V X5R 0805; MANUFACTURER P/N: C2012X5R1V226M125AC; MFG Part number: C1608X5R1A106K080AC; Manufacturer: TDK CORPORATION; Part No.: C1608X5R0J226M080AC; Voltage: 10V
C147 C148 = C_np: CAP CER 22UF 35V X5R 1206; Descriptions: CAP CER 22UF 35V X5R 1206; MANUFACTURER P/N: C2012X5R1V226M125AC; MFG Part number: C3216X5R1V226M160AC; Manufacturer: TDK CORPORATION; Part No.: C1608X5R0J226M080AC; Voltage: 35V
D22 D36 = BZX84C18_SOT_1: DIODE SCHOTTKY 30V 5A SOD128; ALTERNATE PART NUMBER: RBR5LAM30BTR; Alternate Manufacturer: Rohm Semiconductors.; Alternate Mfr Part #: RBR5LAM30BTR; DIGI-KEY PART NO: 568-6519-1-ND; Manufacturer: NXP Semiconductors; Price: 0.48
D37 = BZX84C18_SOT_1: TVS DIODE 24VWM 50VC DO214AA; DIGI-KEY PART NO: 497-3140-1-ND; Manufacturer: STMicroelectronics; Price: 0.42
24VP0 DC_PWR1 TP5 TP7 USB_P_PWR = TEST_POINT: TEST POINT PC MINI .040"D RED; CLASS: DISCRETE; MFG Part number: 5000; Manufacturer: Keystone Electronics; Mfr_Name: Keystone Electronics; Mfr_Part_Number: 5000; PART_NUMBER: 5000; Package Type: TH; Part Number: 400-00001; Section: Power Supply
L4 = INDUCTOR: FIXED IND 3.3UH 8A 20.9 MOHM SMD; Cost: .01; Manufacturer: VISHAY DALE; Tolerance: NA; Voltage: NA
L5 = INDUCTOR: FIXED IND 1.5UH 3.8A 32 mOHM SMD; Cost: .01; MFG Part number: IHLP1212BZER1R5M11; Manufacturer: VISHAY DALE; Part No.: IHLP1212BZER1R5M11; Part Number: IHLP1212BZER1R5M11; Tolerance: NA; Voltage: NA
R162 R173 R180 = R: RES SMD 100K OHM 5% 1/10W 0402; MFG Part number: ERJ-2GEJ104X; Manufacturer: Panasonic Electronic Components; Part No.: ERJ-2GEJ104X
R164 = R: RES SMD 3.3 OHM 1% 1/6W 0402; MFG Part number: RL0510S-3R3-F; Manufacturer: Susumu; Part No.: RL0510S-3R3-F
R165 = R: RES SMD 10K OHM 1% 1/16W 0402; MFG Part number: RC1005F103CS; Manufacturer: Samsung Electro-Mechanics America, Inc
R166 = R: RES SMD 3M OHM 1% 1/16W 0402; MFG Part number: RC1005F305CS; Manufacturer: Samsung Electro-Mechanics America, Inc
R168 = R: BOM_IG: NO LOAD; DNL: DNL; Part No.: ERJ-1GEF1152C
R169 = R: RES SMD 41.2K OHM 1% 1/16W 0402; Alternate Manufacturer: Samsung Electro-Mechanics; Alternate Mfr Part #: RC1005F4122CS; MFG Part number: RC0402FR-0741K2L; Manufacturer: YAGEO; Part No.: RC0402FR-0741K2L
R170 = RESD,0402,5%,1_32W,10K: RES SMD 330 OHM 5% 1/10W 0603; Alternate Manufacturer: Stackpole Electronics Inc.; Alternate Mfr Part #: RMCF0603JT330R; DIGI-KEY PART NO: 311-330GRCT-ND; MFG Part number: RC0603JR-07330RL; Manufacturer: Yageo; Price: 0.1; Tolerance: 5%
R171 R174 = R: BOM_IG: NO LOAD; DNL: DNL; Part No.: ERJ-1GEF4322C
R172 = R: BOM_IG: NO LOAD; DNP: DNP; Part No.: ERJ-1GEF4322C
R176 = R: BOM_IG: NO LOAD; Part No.: ERJ-1GEF4322C
R179 = R: RES SMD 499K OHM 1% 1/16W 0402; MFG Part number: RC0402FR-07499KL; Manufacturer: YAGEO; Part No.: ERJ-1GEF4993C
R181 = R: RES SMD 200K OHM 1% 1/10W 0402; MFG Part number: ERJ-2RKF2003X; Manufacturer: PANASONIC ELECTRONIC COMPONENTS; Part No.: ERJ-1GEF2003C
R182 = R: RES SMD 44.2K OHM 1% 1/16W 0402; MFG Part number: RC0402FR-0744K2L; Manufacturer: YAGEO; Part No.: ERJ-1GEF4422C
R183 = R: RES SMD 5.6K OHM 5% 1/16W 0402; MFG Part number: RC0402JR-075K6L; Manufacturer: YAGEO; Part No.: RC0402JR-075K6L
TP6 = TEST_POINT: TEST POINT PC MINI .040"D YELLOW; CLASS: DISCRETE; DIGI-KEY PART NO: 36-5004-ND; DNP: DNP; MFG Part number: 5004; Manufacturer: Keystone Electronics; Mfr_Name: Keystone Electronics; Mfr_Part_Number: 5000; PART_NUMBER: 5000; Package Type: TH; Part Number: 400-00001; Price: 0.36; Section: Power Supply
U12 = mp8759_0: IC SYNC BUCK CONVERTER 8A 26V; Manufacturer: MPS
U13 = MP2162: IC REG BUCK ADJ 2A SYNC QFN; MFG Part number: MP2162GQH; Manufacturer: MPS
C15-C21 = 10uF-50V-10%-X5R-1206: CAP CER 10UF 25V X5R 0805; Alternate Manufacturer: TDK Corporation; Alternate Mfr Part #: C2012X5R1V106K085AC; MFG Part number: CL21A106KAYNNNE; Manufacturer: Samsung Electro-Mechanics; PART_NUMBER: C3216X5R1H106K160AB; Voltage: 25V
C22 C23 C52 = CAP_TH_Rad_8mmDia_3_5mmPitch: 100µF 35V Aluminum - Polymer Capacitors Radial; DIGI-KEY PART NO: 493-6630-1-ND; MFG Part number: RL81V101MDN1KX; MFG Part#: RL81V101MDN1KX; Manufacturer: Nichicon; Price: 2.12; Voltage: 35V
C26 C27 = Capacitor_402_Generic_SMD: BOM_IG: NO LOAD; Voltage: 50V
C47 = CAP_NP: CAP CER 2.2UF 50V X7R 0805; DIGI-KEY PART NO: 445-172488-2-ND; MFG Part number: C2012X7R1H225M125AE; Manufacturer: TDK Corporation; Price: 0.73; VOLTAGE: 50V
C48 = CAP_NP: CAP CER 0.047UF 50V X7R 0603; DIGI-KEY PART NO: 490-4934-2-ND; MFG Part number: GCM188R71H473KA55D; Manufacturer: Murata Electronics North America; Price: 0.73; VOLTAGE: 50V
C49 C59 C61 = Capacitor_402_Generic_SMD: CAP CER 0.1UF 50V X7R 0402; MFG Part number: C1005X7R1H104K050BB; Manufacturer: TDK CORPORATION; Voltage: 50V
C51 = 10uF-50V-10%-X5R-1206: CAP CER 10UF 50V X5R 1206; Alternate Manufacturer: TDK Corporation; Alternate Mfr Part #: CGA5L1X7R1V106K160AE; Dist1_PN: 490-12456-2-ND; MFG Part number: GRT31CR61H106KE01L; Manufacturer: Murata Electronics North America; PART_NUMBER: C3216X5R1H106K160AB; Voltage: 50V
C53 = Capacitor_402_Generic_SMD: CAP CER 10PF 50V NP0 0402; Alternate Manufacturer: Murata Electronics North America; Alternate Mfr Part #: GCQ1555C1H100JB01D; MFG Part number: GRM1555C1H100JA01D; MFG Part#: GRM1555C1H100JA01D; Manufacturer: Murata Electronics North America; Voltage: 50V
C54 = Capacitor_402_Generic_SMD: 1500pF 50V Ceramic Capacitor X7R 0402; MFG Part number: GRM155R71H152KA01D; MFG Part#: GRM155R71H152KA01D; Manufacturer: Murata Electronics North America; Voltage: 50V
C55 = CAP_NP: BOM_IG: NO LOAD; Package: 402; Part Type: Surface Mount; Voltage: 50V
C56 = CAP_NP: 1000pF 50V Ceramic Capacitor X7R 0402; Alternate Manufacturer: Murata Electronics North America; Alternate Mfr Part #: GCM155R71H102KA37D; MFG Part number: GRM155R71H102KA01D; Manufacturer: Murata Electronics North America; Package: 402; Part Type: Surface Mount; Voltage: 50V
C57 C58 = Capacitor_402_Generic_SMD: CAP CER 10000PF 25V X7R 0402; Alternate Manufacturer: Vishay Vitramon; Alternate Mfr Part #: VJ0402Y103KXXAC; MFG Part number: 04023C103KAT2A; Manufacturer: AVX CORPORATION; Voltage: 50V
C60 C62 = Capacitor_603_Generic_SMD: CAP CER 4.7UF 10V X5R 0402; Alternate Manufacturer: Murata Electronics North America; Alternate Mfr Part #: ZRB15XR61A475KE01D; MFG: TDK; MFG Part number: C1005X5R1A475M050BC; MFG Part#: C1005X5R1A475M050BC; Manufacturer: TDK CORPORATION; Package: 0402; Voltage: 6.3V
D1 D2 = BZX84C18_SOT_1: DIODE SCHOTTKY 30V 5A SOD128; Alternate Manufacturer: Rohm Semiconductors.; Alternate Mfr Part #: RBR5LAM30BTR; DIGI-KEY PART NO: 568-6519-1-ND; Manufacturer: NXP Semiconductors; Price: 0.48
D11 = BZX84C18_SOT_2: TVS DIODE 24VWM 50VC DO214AA; Manufacturer: STMicroelectronics; Mfr_Name: STMicroelectronics
D12 = Diode_0: DIODE GEN PURP 75V 150MA SOD323F; BOM_IGNORE: DNL; Manufacturer: ON Semiconductor
D13 = Diode_0: DIODE GEN PURP 75V 150MA SOD323F; Manufacturer: ON Semiconductor
D14 = Diode_Zener_0: DIODE ZENER 12V 250MW SOT23-3; Alternate Manufacturer: ON Semiconductor; Alternate Mfr Part #: BZX84B12LT1G; Manufacturer: ON Semiconductor; Vz: 12V
D15 D16 = Schottky_Diode_-_SOD-323: DIODE SCHOTTKY 40V 250MA SOD323; DIGI-KEY PART NO: NSR0240HT1GOSCT-ND; MFG Part number: NSR0240HT1G; Manufacturer: ON SEMICONDUCTOR; Price: 0.25
J1 = TERMINAL_BLOCK: TERMINAL BLOCK 5MM VERT 2POS PCB; DIGI-KEY PART NO: ED2600-ND; Manufacturer: On Shore Technology Inc.; Price: 0.46
J2 = CONN_JACK_PWR_2: CONN PWR JACK DC RIGHT ANGLE THROUGH HOLE; DIGI-KEY PART NO: 732-5930-ND; Manufacturer: Wurth electronics; Price: 1.04
L3 = Ind_Wurth_0: 4.2µH Shielded Wirewound Inductor 11A 7.1 mOhm Nonstandard; DCR: 7.1 mOhm; DIGI-KEY PART NO: 732-1170-1-ND; Imax: 11 A; MFG Part number: 744325420; Manufacture PN: 744325420; Manufacturer: Wurth Electronics Inc; Price: 4.01
NT1-NT4 = Net_Tie: DNP: DNP; Package: 5mil; Part Type: Surface Mount
Q1-Q4 = N-Channel_u8-FL_0: MOSFET N-CH 60V 20A 8WDFN; DIGI-KEY PART NO: NVTFS5826NLTAG-ND; Manufacturer: ON SEMICONDUCTOR; Rds on: 24 mOhm; Voltage: 30V
Q11 = NFET_BSZ110N06NS3: MOSFET N-CH 60V 20A 8TSDSON; MFG Part number: BSZ110N06NS3GATMA1
R20 R21 = Resistor_1206_Generic_SMD_4: 0.005 Ohms 1 % 1206 SMD; MFG: Vishay; MFG Part number: WSL12065L000FEA18; MFG Part#: WSL12065L000FEA18; Manufacturer: VISHAY DALE; Package: 1206; Wattage: 1/2 W
R24 R25 = Resistor_402_Generic_SMD_0: BOM_IG: NO LOAD
R62 = R: RES SMD 0.0 OHM JUMPER 1/8W 0805; DIGI-KEY PART NO: 311-0.0ARCT-ND; DNP: DNP; MFG Part number: RC0805JR-070RL; Manufacturer: Yageo; Price: 0.1
R63 = RESISTOR_v2: RES SMD 100K OHM 0.5% 1/16W 0603; DIGI-KEY PART NO: 1276-3431-1-ND; MFG Part number: RR0816P-104-D; Manufacturer: Susumu; Price: 0.1
R64 = RESISTOR_v2: RES SMD 200K OHM 0.5% 1/16W 0603; DIGI-KEY PART NO: 1276-3431-1-ND; MFG Part number: CPF0603B200KE1; Manufacturer: TE Connectivity Passive Product; Price: 0.1
R65 = RESISTOR_v2: RES SMD 10K OHM 1% 1/16W 0402; DIGI-KEY PART NO: 1276-3431-1-ND; MFG Part number: RC1005F103CS; Manufacturer: Samsung Electro-Mechanics America, Inc; Price: 0.1
R66 R76 R78 R80 R81 R83 R85 = RESISTOR_v2: RES 0.0 OHM 1/16W JUMP 0402 SMD; DIGI-KEY PART NO: 541-0.0JCT-ND; MFG Part number: CRCW04020000Z0ED; Manufacturer: Vishay Dale; Price: 0.074
R67 = RESISTOR: RES SMD 24.3K OHM 1% 1/16W 0402; Alternate Manufacturer: Yageo; Alternate Mfr Part #: RC0402FR-0724K3L; MFG Part number: RMCF0402FT24K3; Manufacturer: Stackpole Electronics Inc; Package: 402; Part Type: Surface Mount
R68 = Resistor_402_Generic_SMD: RES SMD 20.5K OHM 1% 1/16W 0402; MFG Part number: RC0402FR-0720K5L; Manufacturer: YAGEO
R69 = RESISTOR: RES SMD 20K OHM 1% 1/10W 0402; MFG Part number: ERJ-2RKF2002X; Manufacturer: PANASONIC ELECTRONIC COMPONENTS; Package: 402; Part Type: Surface Mount
R70 = RESISTOR: RES SMD 20.5K OHM 1% 1/16W 0402; MFG Part number: RC0402FR-0720K5L; Manufacturer: YAGEO; Package: 402; Part Type: Surface Mount
R71 = RESISTOR: RES SMD 90.9K OHM 1% 1/10W 0402; MFG Part number: ERJ-2RKF9092X; Manufacturer: PANASONIC ELECTRONIC COMPONENTS; Package: 402; Part Type: Surface Mount
R72-R75 = Resistor_402_Generic_SMD: RES SMD 10 OHM 1% 1/10W 0402; MFG Part number: ERJ-2RKF10R0X; Manufacturer: PANASONIC ELECTRONIC COMPONENTS
R77 R79 = Resistor_402_Generic_SMD: RES SMD 4.02 OHM 1% 1/16W 0402; MFG Part number: CRCW04024R02FKED; Manufacturer: VISHAY DALE
R82 = Resistor_402_Generic_SMD: RES SMD 1 OHM 5% 1/16W 0402; MFG Part number: RC0402JR-071RL; Manufacturer: YAGEO
TP4 = TEST_POINT: TEST POINT PC MINI .040"D YELLOW; DIGI-KEY PART NO: 36-5004-ND; MFG Part number: 5004; Manufacturer: Keystone Electronics; Price: 0.36
U9 = NCP3231_2: USB Power Delivery 4-Switch Buck Boost Controller; Manufacturer: ON SEMICONDUCTOR
V2 = TEST_POINT: TEST POINT PC MINI .040"D YELLOW; DIGI-KEY PART NO: 36-5004-ND; DNP: DNP; MFG Part number: 5004; Manufacturer: Keystone Electronics; Price: 0.36
C63 C64 = CAP_NP: CAP CER 0.1UF 10V 10% X7R 0402; DIGI-KEY PART NO: 445-4958-1-ND; DNP: DNP; MFG Part number: C1005X7R1A104K050BB; Manufacturer: TDK Corporation; Price: 0.1; Tolerance: 10%; VOLTAGE: 10V
C65 = CAP_NP: CAP CER 1UF 35V X7R 0603; DIGI-KEY PART NO: 445-7414-1-ND; DNP: DNP; MFG Part number: C1608X7R1V105K080AC; Manufacturer: TDK Corporation; Price: 0.24; VOLTAGE: 35V
C115 = 10uF-50V-10%-X5R-1206: CAP CER 4.7UF 50V X7R 1210; Alternate Manufacturer: Taiyo Yuden; Alternate Mfr Part #: UMK325B7475MMHT; DIGI-KEY PART NO: 490-10962-1-ND; MFG Part number: GRJ32ER71H475KE11L; Manufacturer: Murata Electronics North America; Price: 0.89; Voltage: 50V
C95 C96 C116 = CAP_NP: CAP CER 2200PF 2KV 10% X7R 1808; Alternate Manufacturer: KEMET; Alternate Mfr Part #: C1808X222KGRACTU; DIGI-KEY PART NO: 709-1306-1-ND; MFG Part number: 202R29W222KV4E; Manufacturer: Johanson Dielectrics Inc.; Price: 0.49; Tolerance: 10%; VOLTAGE: 2KV
D17 = BZX84C18_SOT_1: DIODE SCHOTTKY 30V 5A SOD128; DIGI-KEY PART NO: 568-6519-1-ND; DNP: DNP; Manufacturer: NXP Semiconductors; Price: 0.48
D27 = BZX84C18_SOT_1_v2: TVS DIODE 24VWM 38.9VC SMB; DIGI-KEY PART NO: SMBJ24CA-E3/52GICT-ND; DNP: DNP; Manufacturer: Vishay Semiconductor Diodes Division; Price: 0.41
D28-D35 = BZX84C18_SOT_1_v2: TVS DIODE 5.5VWM 14VC TSLP2-2; DIGI-KEY PART NO: ESD105B102ELE6327XTMA1CT-ND; DNP: DNP; MFG Part number: ESD105B102ELE6327XTMA1; Manufacturer: Infineon Technologies; Price: 0.45
J17 = TERMINAL_BLOCK: TERM BLOCK PCB 2POS 5.0MM GREEN; DIGI-KEY PART NO: 277-1667-ND; Manufacturer: Phoenix Contact; Price: 0.37
J18 = USB-PD_TYPE-C_20: USB TYP C TP MNT DL RW SMT RECEP; DIGI-KEY PART NO: 670-2794-1-ND; Manufacturer: JAE Electronics; Price: 2.61
Q5-Q8 = MOSFET_P_SO8_1: MOSFET P-CH 30V 8.7A PWRDI3333-8; DIGI-KEY PART NO: DMP3036SFG-7DITR-ND; Manufacturer: Diodes Incorporated
R23 = Resistor_402_Generic_SMD: RES 0.005 OHM 1% 2W 2512; MFG: Stackpole Electronics Inc.; MFG Part number: CSNL2512FT5L00; Manufacturer: Stackpole Electronics Inc.; Package: 2512 (6432 Metric); Tolerance: 1%; Wattage: 2W
R84 R86 = R: RES 49.9K OHM 1/10W 1% 0402 SMD; MFG Part Number: ERJ-2RKF4992X; Manufacturer: Panasonic; PART_NUMBER: ERJ-2RKF4992X; Power_Rating: 1/10W; Tolerance: 1%; Voltage: 3.3V
R137 R155 = 10K-1_16W-5%-0603: RES SMD 100K OHM 5% 1/10W 0402; DIGI-KEY PART NO: P100KJCT-ND; MFG Part number: ERJ-2GEJ104X; Manufacturer: Panasonic Electronic Components; Price: 0.1
R156 R157 = Res_0R_1_16W_Jumper_0402: RES SMD 2M OHM 1% 1/16W 0402; MFG Part number: RC1005F205CS; Manufacturer: Samsung Electro-Mechanics America, Inc; Manufacturer Part Number: RC0402JR-072ML
C37-C44 = CAP_NP: CAP CER 0.22UF 16V 10% X7R 0402; Alternate Manufacturer: TDK Corporation; Alternate Mfr Part #: C1005X7R1C224K050BC; DIGI-KEY PART NO: 311-1708-1-ND; MFG Part number: CC0402KRX7R7BB224; Manufacturer: Yageo; Price: 0.1; Tolerance: 10%; VOLTAGE: 16V
C84-C93 = CAP_NP: CAP CER 0.1UF 10V 10% X7R 0402; Alternate Manufacturer: Samsung Electro-Mechanics; Alternate Mfr Part #: CL05B104KP5NNNC; DIGI-KEY PART NO: 445-4958-1-ND; MFG Part number: C1005X7R1A104K050BB; Manufacturer: TDK Corporation; Price: 0.1; Tolerance: 10%; VOLTAGE: 10V
DP_PWR = T_POINT_R: TEST POINT PC MINI .040"D RED; DIGI-KEY PART NO: 36-5000-ND; DNL: DNL; MFG Part number: 5000; Manufacturer: Keystone Electronics; Price: 0.36
J14 = USB3_TYPE-B_0: Connector Receptacle USB TypeB 3.1, Super Speed 9 Position Through Hole, Right Angle, Horizontal; DIGI-KEY PART NO: GSB4211311WEU-ND; Manufacturer: Amphenol Commercial Products; Price: 2.54
J15 = DISPLAY_PORT_CONN_10: Connector Receptacle DisplayPort 20 Position Surface Mount, Right Angle, Horizontal; DIGI-KEY PART NO: WM19271CT-ND; MFG Part number: 472720001; Manufacturer: Molex, LLC; Price: 5.3
R22 R44 R119 R121 R124 = RESISTOR_v2: RES SMD 100K OHM 5% 1/10W 0402; DIGI-KEY PART NO: P100KJCT-ND; MFG Part number: ERJ-2GEJ104X; Manufacturer: Panasonic Electronic Components; Price: 0.1; Tolerance: 5%
R38 R41-R43 R46-R53 R131-R134 = R: RES 0.0 OHM 1/16W JUMP 0402 SMD; DIGI-KEY PART NO: 541-0.0JCT-ND; MFG Part number: CRCW04020000Z0ED; Manufacturer: Vishay Dale; Price: 0.074
R120 R122 R123 = RESISTOR_v2: RES SMD 100K OHM 5% 1/10W 0402; DIGI-KEY PART NO: P100KJCT-ND; DNP: DNP; MFG Part number: ERJ-2GEJ104X; Manufacturer: Panasonic Electronic Components; Price: 0.1; Tolerance: 5%
R127 = RESISTOR_v2: RES SMD 10K OHM 1% 1/16W 0402; DIGI-KEY PART NO: 1276-3431-1-ND; DNP: DNP; MFG Part number: RC1005F103CS; Manufacturer: Samsung Electro-Mechanics America, Inc; Price: 0.1; Tolerance: 1%
R135 R136 = RESISTOR_v2: RES SMD 1M OHM 1% 1/10W 0603; DIGI-KEY PART NO: 311-1.00MHRCT-ND; MFG Part number: RC0603FR-071ML; Manufacturer: Yageo; Price: 0.1; Tolerance: 1%
R158-R161 = R: RES SMD 200K OHM 1% 1/10W 0402; DNP: DNP; MFG Part number: ERJ-2RKF2003X; Manufacturer: Panasonic Electronic Components; Part No.: ERJ-1GEF2003C
U6 U7 = DT1240-04LP-UDFN10: TVS DIODE 5.5VWM 11VC DFN; MFG Part Number: DT1240-04LP; Manufacturer: Diodes Incorporated
U8 = PI3DPX1205AZLBE-TQFN40_0: 10G MUX; MFG Part Number: PI3DPX1205AZLBE; Manufacturer: Pericom

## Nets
5V: C126.1 C127.1 R177.1 R179.1 R180.1 U13.7(VIN)
GND: C15.2 C16.2 C17.2 C18.2 C19.2 C20.2 C21.2 C22.2 C23.2 C24.2 C25.2 C26.2 C27.2 C28.2 C35.1 C36.1 C45.1 C46.1 C49.2 C50.1 C51.2 C52.2 C53.2 C54.2 C55.2 C56.2 C60.2 C62.2 C63.1 C64.1 C84.1 C85.1 C86.1 C87.1 C88.1 C89.1 C90.1 C91.1 C94.1 C95.1 C96.1 C97.1 C98.1 C99.1 C100.1 C101.2 C102.2 C103.1 C112.1 C113.1 C114.1 C115.1 C116.2 C120.2 C125.1 C126.2 C127.2 C128.2 C142.2 C144.2 C145.2 C146.1 C147.2 C148.2 D26.A(ANODE) D27.A(ANODE) D28.A(ANODE) D29.A(ANODE) D30.A(ANODE) D31.A(ANODE) D32.A(ANODE) D33.A(ANODE) D34.A(ANODE) D35.A(ANODE) D37.A(ANODE) J1.2 J14.4(GND) J14.7(GND_DRAIN) J15.2(GND_1) J15.5(GND_2) J15.8(GND_3) J15.11(GND_4) J15.16(GND_5) J15.19(RETURN) J16.2 J17.2 J18.A1(GND_1) J18.A12(GND_2) J18.B1(GND_3) J18.B12(GND_4) LED2.2(CATHODE) LED4.2(CATHODE) LED5.2(CATHODE) Q3.1(SOURCE) Q3.2(SOURCE) Q3.3(SOURCE) Q4.1(SOURCE) Q4.2(SOURCE) Q4.3(SOURCE) Q11.5(D) Q11.6(D) Q11.7(D) Q11.8(D) R44.2 R62.1 R65.2 R66.1 R67.2 R69.1 R70.1 R119.2 R121.2 R124.2 R135.1 R136.1 R137.2 R149.2 R155.2 R156.2 R157.2 R158.2 R159.2 R160.2 R161.2 R162.2 R165.2 R174.2 R176.2 R182.2 R183.2 SW2.1 U6.3(VSS) U6.8(VSS) U7.3(VSS) U7.8(VSS) U8.41(HGND) U9.3(PGND1) U9.13(AGND1) U9.14(AGND2) U9.22(PGND2) U9.27(DBOUT) U9.28(DBIN) U9.33(EPAGND) U11.EPAD(VSS) U12.2(PGND) U12.10(AGND) U13.3(AGND) U13.5(PGND)
GND_EARTH: C116.1 J18.SH_1(SH1) J18.SH_2(SH2) J18.SH_3(SH3) J18.SH_4(SH4) J18.SH_5(SH5) J18.SH_6(SH6) R155.1
V3P3: C45.2 C46.2 C84.2 C85.2 C86.2 C87.2 C88.2 C89.2 C90.2 C91.2 C128.1 C142.1 J10.1 R22.1 R54.2 R120.1 R122.1 R123.1 R127.1 R139.1 R140.1 R147.1 R178.1 TP7.1 U8.10(VDD33) U8.14(VDD33) U8.17(VDD33) U8.26(VDD33) U8.32(VDD33) U8.35(VDD33) U8.38(VDD33)
V5P0: C35.2 C36.2 C98.2 C99.2 D9.A R167.1 R170.2 R177.2 TP5.1 U11.8(VCONN_SOURCE)
V24P0: 24VP0.1 C19.1 C20.1 C21.1 C22.1 C49.1 C50.2 C51.1 C52.1 D1.C(CATHODE) D2.C(CATHODE) D11.2(CATHODE) D12.1(K) D36.A(ANODE) NT2.1 R20.2 R63.2 R64.2 R162.1 U9.6(V1)
VBUS_C_CTRL: R85.2 U11.12(VBUS_C_CTRL)
VBUS_P_CTRL: R83.2 U11.11(VBUS_P_CTRL)
VCC: C60.1 R82.1 U9.30(VCC)
VDDD: C112.2 C113.2 C114.2 U11.31(VDDD) U11.32(VDDIO)
VDDIO: R40.2 R143.1
CC1: C100.2 D34.C(CATHODE) J18.A5(CC1) U11.9(CC1)
CC2: C97.2 D35.C(CATHODE) J18.B5(CC2) U11.7(CC2)
CON_RX1+: C37.1 U8.7(RX1P)
CON_RX1-: C38.1 U8.8(RX1N)
CON_RX2+: C44.1 U8.16(RX2P)
CON_RX2-: C43.1 U8.15(RX2N)
CON_SBU1: D32.C(CATHODE) J18.A8(SBU1) R157.1
CON_SBU1 (page 06. PERICOM_MUX (OPTIONAL)): R38.1
CON_SBU2: D33.C(CATHODE) J18.B8(SBU2) R156.1
CON_SBU2 (page 06. PERICOM_MUX (OPTIONAL)): R41.1
CON_TX1+: C41.1 U8.11(TX1P)
CON_TX1-: C42.1 U8.12(TX1N)
CON_TX2+: C40.1 U8.20(TX2P)
CON_TX2-: C39.1 U8.19(TX2N)
CSN: NT1.2 R75.1
CSN2: NT3.2 R72.2
CSP: NT4.2 R73.2
CSP1: NT2.2 R74.1
D+_Bot: D28.C(CATHODE) J18.B6(D+) U11.26(D+_BOT)
D+_Host: J14.3(D+) U11.24(D-_SYS)
D+_top: D30.C(CATHODE) J18.A6(D+) U11.28(D+_TOP)
D-_Bot: D29.C(CATHODE) J18.B7(D-) U11.25(D-_BOT)
D-_Host: J14.2(D-) U11.23(D+_SYS)
D-_top: D31.C(CATHODE) J18.A7(D-) U11.27(D-_TOP)
DC_PWR: C147.1 C148.1 D37.C(CATHODE) DC_PWR1.1 R163.1 R166.1 U12.1(VIN)
DCI_CLK: U8.22(DCI_CLK)
DCI_DAT: U8.21(DCI_DAT)
DP_AUXN: J15.17(AUX_CH_N) R22.2 R42.2
DP_AUXP: J15.15(AUX_CH_P) R43.2 R44.1
En_3V3: R180.2 U13.1(EN)
EN_REG: TP4.1 U9.16(EN) U11.5(P1.3)
HGATE1: Q2.4(GATE) R79.1
HGATE2: Q1.4(GATE) R77.2
HOTPLUG_DET: D26.K(CATHODE) R134.2 R147.2 R148.1 R149.1
IN_HPD: R127.2 R133.1 U8.25(IN_HPD)
INT: U9.11(INT)
M0+_C: J15.12(ML_LANE_0P) R51.2
M0-_C: J15.10(ML_LANE_0N) R50.2
M1+_C: J15.9(ML_LANE_1P) R53.2
M1-_C: J15.7(ML_LANE_1N) R52.2
M2+_C: J15.6(ML_LANE_2P) R48.2
M2-_C: J15.4(ML_LANE_2N) R49.2
M3+_C: J15.3(ML_LANE_3P) R46.2
M3-_C: J15.1(ML_LANE_3N) R47.2
Mux_A0: R123.2 R124.1 U8.9(A0)
Mux_A1: R119.1 R120.2 U8.13(A1)
Mux_A2: R121.1 R122.2 U8.18(A2)
Mux_EN: R54.1 U8.29(EN)
PG_3V3: R179.2 U13.8(PG)
PG_5V: R172.1 R173.1 TP6.1
PMG1-S1_SWD_CLK: J16.4 U11.2(P1.0/SWD_CLK)
PMG1-S1_SWD_IO: J16.5 U11.6(P1.4/SWD_IO)
PMG1-S1_XRES: C101.1 J16.3 R143.2 SW2.2 U11.10(XRES)
PMG-S1_SWD_IO: R154.2
RX1+_C: C37.2 J18.B11(RX1+) R160.1 U7.5(I/O4) U7.6(NC4)
RX1-_C: C38.2 J18.B10(RX1-) R161.1 U7.4(I/O3) U7.7(NC3)
RX2+_C: C44.2 J18.A11(RX2+) R158.1 U6.2(I/O2) U6.9(NC2)
RX2-_C: C43.2 J18.A10(RX2-) R159.1 U6.1(I/O1) U6.10(NC1)
SH_GND: C96.2 J15.21(SH1) J15.22(SH2) J15.23(SH3) J15.24(SH4)
SH_USB_B: C95.2 J14.19(SH1) J14.20(SH2) R137.1
SW0_I2C_SCL: R140.2 U8.6(SCL) U9.10(SCL) U11.4(P1.2)
SW0_I2C_SDA: R139.2 U8.5(SDA) U9.9(SDA) U11.3(P1.1)
SWN2: L3.2 Q1.1(SOURCE) Q1.2(SOURCE) Q1.3(SOURCE) Q3.5(DRAIN) Q3.6(DRAIN) Q3.7(DRAIN) Q3.8(DRAIN) R24.1 R81.2 U9.26(VSW2)
TX1+_C: C41.2 J18.A2(TX1+) U7.2(I/O2) U7.9(NC2)
TX1-_C: C42.2 J18.A3(TX1-) U7.1(I/O1) U7.10(NC1)
TX2+_C: C40.2 J18.B2(TX2+) U6.5(I/O4) U6.6(NC4)
TX2-_C: C39.2 J18.B3(TX2-) U6.4(I/O3) U6.7(NC3)
TYPE-C_VBUS: C65.1 C115.2 D27.C(CATHODE) J18.A4(VBUS_1) J18.A9(VBUS_2) J18.B4(VBUS_3) J18.B9(VBUS_4) Q7.5(D) Q7.6(D) Q7.7(D) Q7.8(D) Q7.9(D) Q8.5(D) Q8.6(D) Q8.7(D) Q8.8(D) Q8.9(D) U11.22(VBUS)
USB3.1_RX+: J14.9(STDB_SSRX+) R132.2
USB3.1_RX-: J14.8(STDB_SSRX-) R131.2
USB3.1_TX+: C93.1 J14.6(STDB_SSTX+)
USB3.1_TX-: C92.1 J14.5(STDB_SSTX-)
USB3_VBUS: C94.2 J14.1(VBUS)
USB_C_PWR: C25.1 D22.A(ANODE) J17.1 Q5.5(D) Q5.6(D) Q5.7(D) Q5.8(D) Q5.9(D) R165.1
USB_P_PWR: C15.1 C16.1 C17.1 C18.1 C23.1 C24.1 NT3.1 R21.1 R23.1 R71.2 U11.1(CSP) USB_P_PWR.1
USB_P_PWR_SENSE: Q6.5(D) Q6.6(D) Q6.7(D) Q6.8(D) Q6.9(D) R23.2 U11.40(CSN)
VDRV: C62.1 D15.2(A) D16.2(A) R82.2 U9.29(VDRV)
VSYS: C102.1 C103.2 J10.2 U11.19(VSYS)
VTARG: D10.A J16.1
N11283099: C92.2 U8.23(SSRXN)
N12204873: C93.2 U8.24(SSRXP)
N12259190: R38.2 U8.4(AUXSBU1)
N12259914: R41.2 U8.3(AUXSBU2)
N12532887: R43.1 U8.1(AUXP)
N12533191: R42.1 U8.2(AUXN)
N16938564: C56.1 R67.1 U9.18(CS2)
N16938596: NT4.1 Q1.5(DRAIN) Q1.6(DRAIN) Q1.7(DRAIN) Q1.8(DRAIN) R21.2
N16938602: C55.1 R66.2 U9.7(CS1)
N16938820: Q3.4(GATE) R76.2
N16938822: R76.1 U9.23(LSG2)
N16938836: R78.2 U9.2(LSG1)
N16938910: C58.2 R74.2 U9.5(CSP1)
N16939092: R79.2 U9.1(HSG1)
N16939119: R77.1 U9.24(HSG2)
N16939123: L3.1 Q2.1(SOURCE) Q2.2(SOURCE) Q2.3(SOURCE) Q4.5(DRAIN) Q4.6(DRAIN) Q4.7(DRAIN) Q4.8(DRAIN) R25.1 R80.2 U9.31(VSW1)
N16939225: C59.1 R80.1
N16939232: C61.1 R81.1
N16939240: C61.2 D16.1(K) U9.25(BST2)
N16939242: R69.2 R70.2 R71.1 U9.19(V2) V2.1
N16939268: Q4.4(GATE) R78.1
N16939278: C57.1 R73.1 U9.21(CSP2)
N16939387: C54.1 R68.2
N16939401: C53.1 R68.1 U9.15(COMP)
N16939488: C59.2 D15.1(K) U9.32(BST1)
N16939601: C57.2 R72.1 U9.20(CSN2)
N16939747: C58.1 R75.2 U9.4(CSN1)
N16939859: NT1.1 Q2.5(DRAIN) Q2.6(DRAIN) Q2.7(DRAIN) Q2.8(DRAIN) R20.1
N17095971: C26.1 R24.2
N17096059: C27.1 R25.2
N17124870: J15.18(HotPlugDetect) R133.2 R134.1
N17152056: D9.C(K) D10.C(K) J10.3
N17169580: C63.2 D17.C(CATHODE) Q5.4(G) Q7.4(G) R85.1 R86.2
N17169737: C64.2 Q6.4(G) Q8.4(G) R83.1 R84.2
N17170568: C65.2 D17.A(ANODE)
N17325643: R132.1 U8.28(SSTXP)
N17325676: R131.1 U8.27(SSTXN)
N17325747: R53.1 U8.30(DP1P)
N17325778: R52.1 U8.31(DP1N)
N17325809: R51.1 U8.33(DP0P)
N17325833: R50.1 U8.34(DP0N)
N17325857: R49.1 U8.36(DP2N)
N17325881: R48.1 U8.37(DP2P)
N17325903: R47.1 U8.39(DP3N)
N17325927: R46.1 U8.40(DP3P)
N17456012: C47.2 D11.1(ANODE) D14.1(ANODE) J2.2 J2.3 Q11.1(S) Q11.2(S) Q11.3(S) R62.2
N17456029: C48.1 R65.1
N17456108: C47.1 D12.2(A) D13.1(K) R63.1
N17457179: D2.A(ANODE) J2.1
N17475903: LED2.1(ANODE) R40.1
N17575637: Q6.1(S) Q6.2(S) Q6.3(S) Q8.1(S) Q8.2(S) Q8.3(S) R84.1
N17575889: Q5.1(S) Q5.2(S) Q5.3(S) Q7.1(S) Q7.2(S) Q7.3(S) R86.1
N17640817: R148.2 U11.18(P3.0)
N17709315: C28.1 U11.33(VCCD)
N17727999: LED4.1(ANODE) R154.1
N17734897: D22.C(CATHODE) D36.C(CATHODE) R163.2
N17735055: C120.1 U12.9(VCC)
N17735084: C117.2 L4.1 R168.1 U12.7(SW)
N17735090: C121.2 C125.2 C144.1 C145.1 C146.2 L4.2 R167.2 R169.1 U12.5(OUT)
N17735189: C121.1 R168.2 R171.2
N17735223: R166.2 R174.1 U12.12(EN)
N17735274: R173.2 U12.3(PG)
N17735280: R169.2 R171.1 R183.1 U12.11(FB)
N17735282: R172.2 R176.1 U12.6(MODE)
N17735444: L5.1 U13.6(SW)
N17735446: C143.1 L5.2 R178.2 R181.1 U13.4(OUT)
N17735559: C143.2 R181.2 R182.1 U13.2(FB)
N17761512: DP_PWR.1(TP) J15.20(DP_PWR)
N17761513: J15.14(CONFIG2) R135.2
N17761515: J15.13(CONFIG1) R136.2
N17763932: C48.2 D14.3(CATHODE)
N17764760: D13.2(A) Q11.4(G)
N17775613: LED5.1(ANODE) R170.1
N17775616: R164.1 U12.8(BST)
N17775618: C117.1 R164.2
N17786687: D1.A(ANODE) J1.1

Not connected (* = marked no-connect by the designer): D14 2(NC)*; R64 1; U9 8(CLIND)* 12(CFET)* 17(PDRV)*; U11 13(P2.0)* 14(P2.1)* 15(P2.2)* 16(P5.0)* 17(P5.1)* 20(P3.1)* 21(P3.2)* 29(P4.0)* 30(P4.1)* 34(NC1)* 35(NC2)* 36(NC3)* 37(NC4)* 38(P0.0)* 39(P0.1)*; U12 4(NC)*

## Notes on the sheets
sheet 1
- STEP DOWN REGULATORS
- DC/DC Converter - 5V @ 2A
- 1500mA
- Step-Down Regulator - 3.3V/1.5A
sheet 2
- PMG1-S1 DRP REFERENCE DESIGN
- CONTENTS
- PAGE
- DESCRIPTION
- 01
- TITLE & TABLE OF CONTENTS
- 02
- PMG1-S1 CONTROLLER
- 03
- STEP DOWN REGULATORS
- 04
- PD REGULATOR
- 05
- VBUS PROVIDER/CONSUMER FET AND TYPE-C CONNCETOR
- 06
- USB SUPERSPEED AND DISPLAY PORT MUX (Optional)
sheet 3
- PMG1-S1 CONTROLLER
- J10 - VSYS SELECT
  1-2 :    3.3V (default)
  2-3 :    5.V or Programming
  NC :    Dead Battery Testing
- I2C MASTER TO  CONTROL
  MUX and REGULATOR
- USER  LED
- PMG1-S1 POWER ON
- RESET
- PMG1-S1 SWD PROGRAMMING HEADER
- Note: Programming header is needed only during
  development. Not needed in the final product.
sheet 4
- USB SUPERSPEED AND DISPLAY PORT MUX (OPTIONAL)
- Source Application
  HOST               Device
- Use mulitple vias connected to ground plane
  if the ground is not on the same layer as CEXT.
- USB 3.1 Type-B
- *Note 2.
- *Note 5.
- *Note 1, 2, 3.
- *Note 2.
- DISPLAY PORT
- For I2C
  Address
- I2C Slave Addess 7 BIT :  0x50
- ESD DT1240A-04LP
- *Note 4.
- *Note 4.
- *Note 1: This section is required for Design that requires USB3 and DP Alt mode Support .
  *Note 2: Suggest RX1/2 signals are reserved AC coupling to support non-compliant Type-C device.
           RX1/2 AC cap C120, C121, C124, C125 should be replaced by 0ohm resistors when DCI test.
  *Note 3: Recommended AC coupling cap charachters: 0201 or 0402, X5R/X7R.
  *Note 4: Suggest to 0.22uF AC coupling cap to ensure risk free in USB-IF Compliance.
  *Note 5: Reserve 200kohm to support non-compliant Type-C device.
  *Note 6: Suggest MUX_EN to be controlled by GPIO.
sheet 5
- PD REGULATOR
- Power
- 4 to 20V
- I2C ADDRESS 74H
- COLOUR: BLUE
- DNP
- Inrush Limiting
  Circuit
sheet 6
- VBUS PROVIDER/CONSUMER FET AND TYPE-C CONNECTOR
- USB Type-C
- 0603
- 0603
- Gate driver for P-MOSFET is integrated in PMG-S1
  VBUS_P_CTRL is an Active LOW signal
  Needs external pullup resistor
- Provider Path Control
- 0603
- 0603
- 0603
- 0603
- Consumer Path Control
- Gate driver for P-MOSFET is integrated in PMG-S1
  VBUS_C_CTRL is an Active LOW signal
  Needs external pullup resistor
